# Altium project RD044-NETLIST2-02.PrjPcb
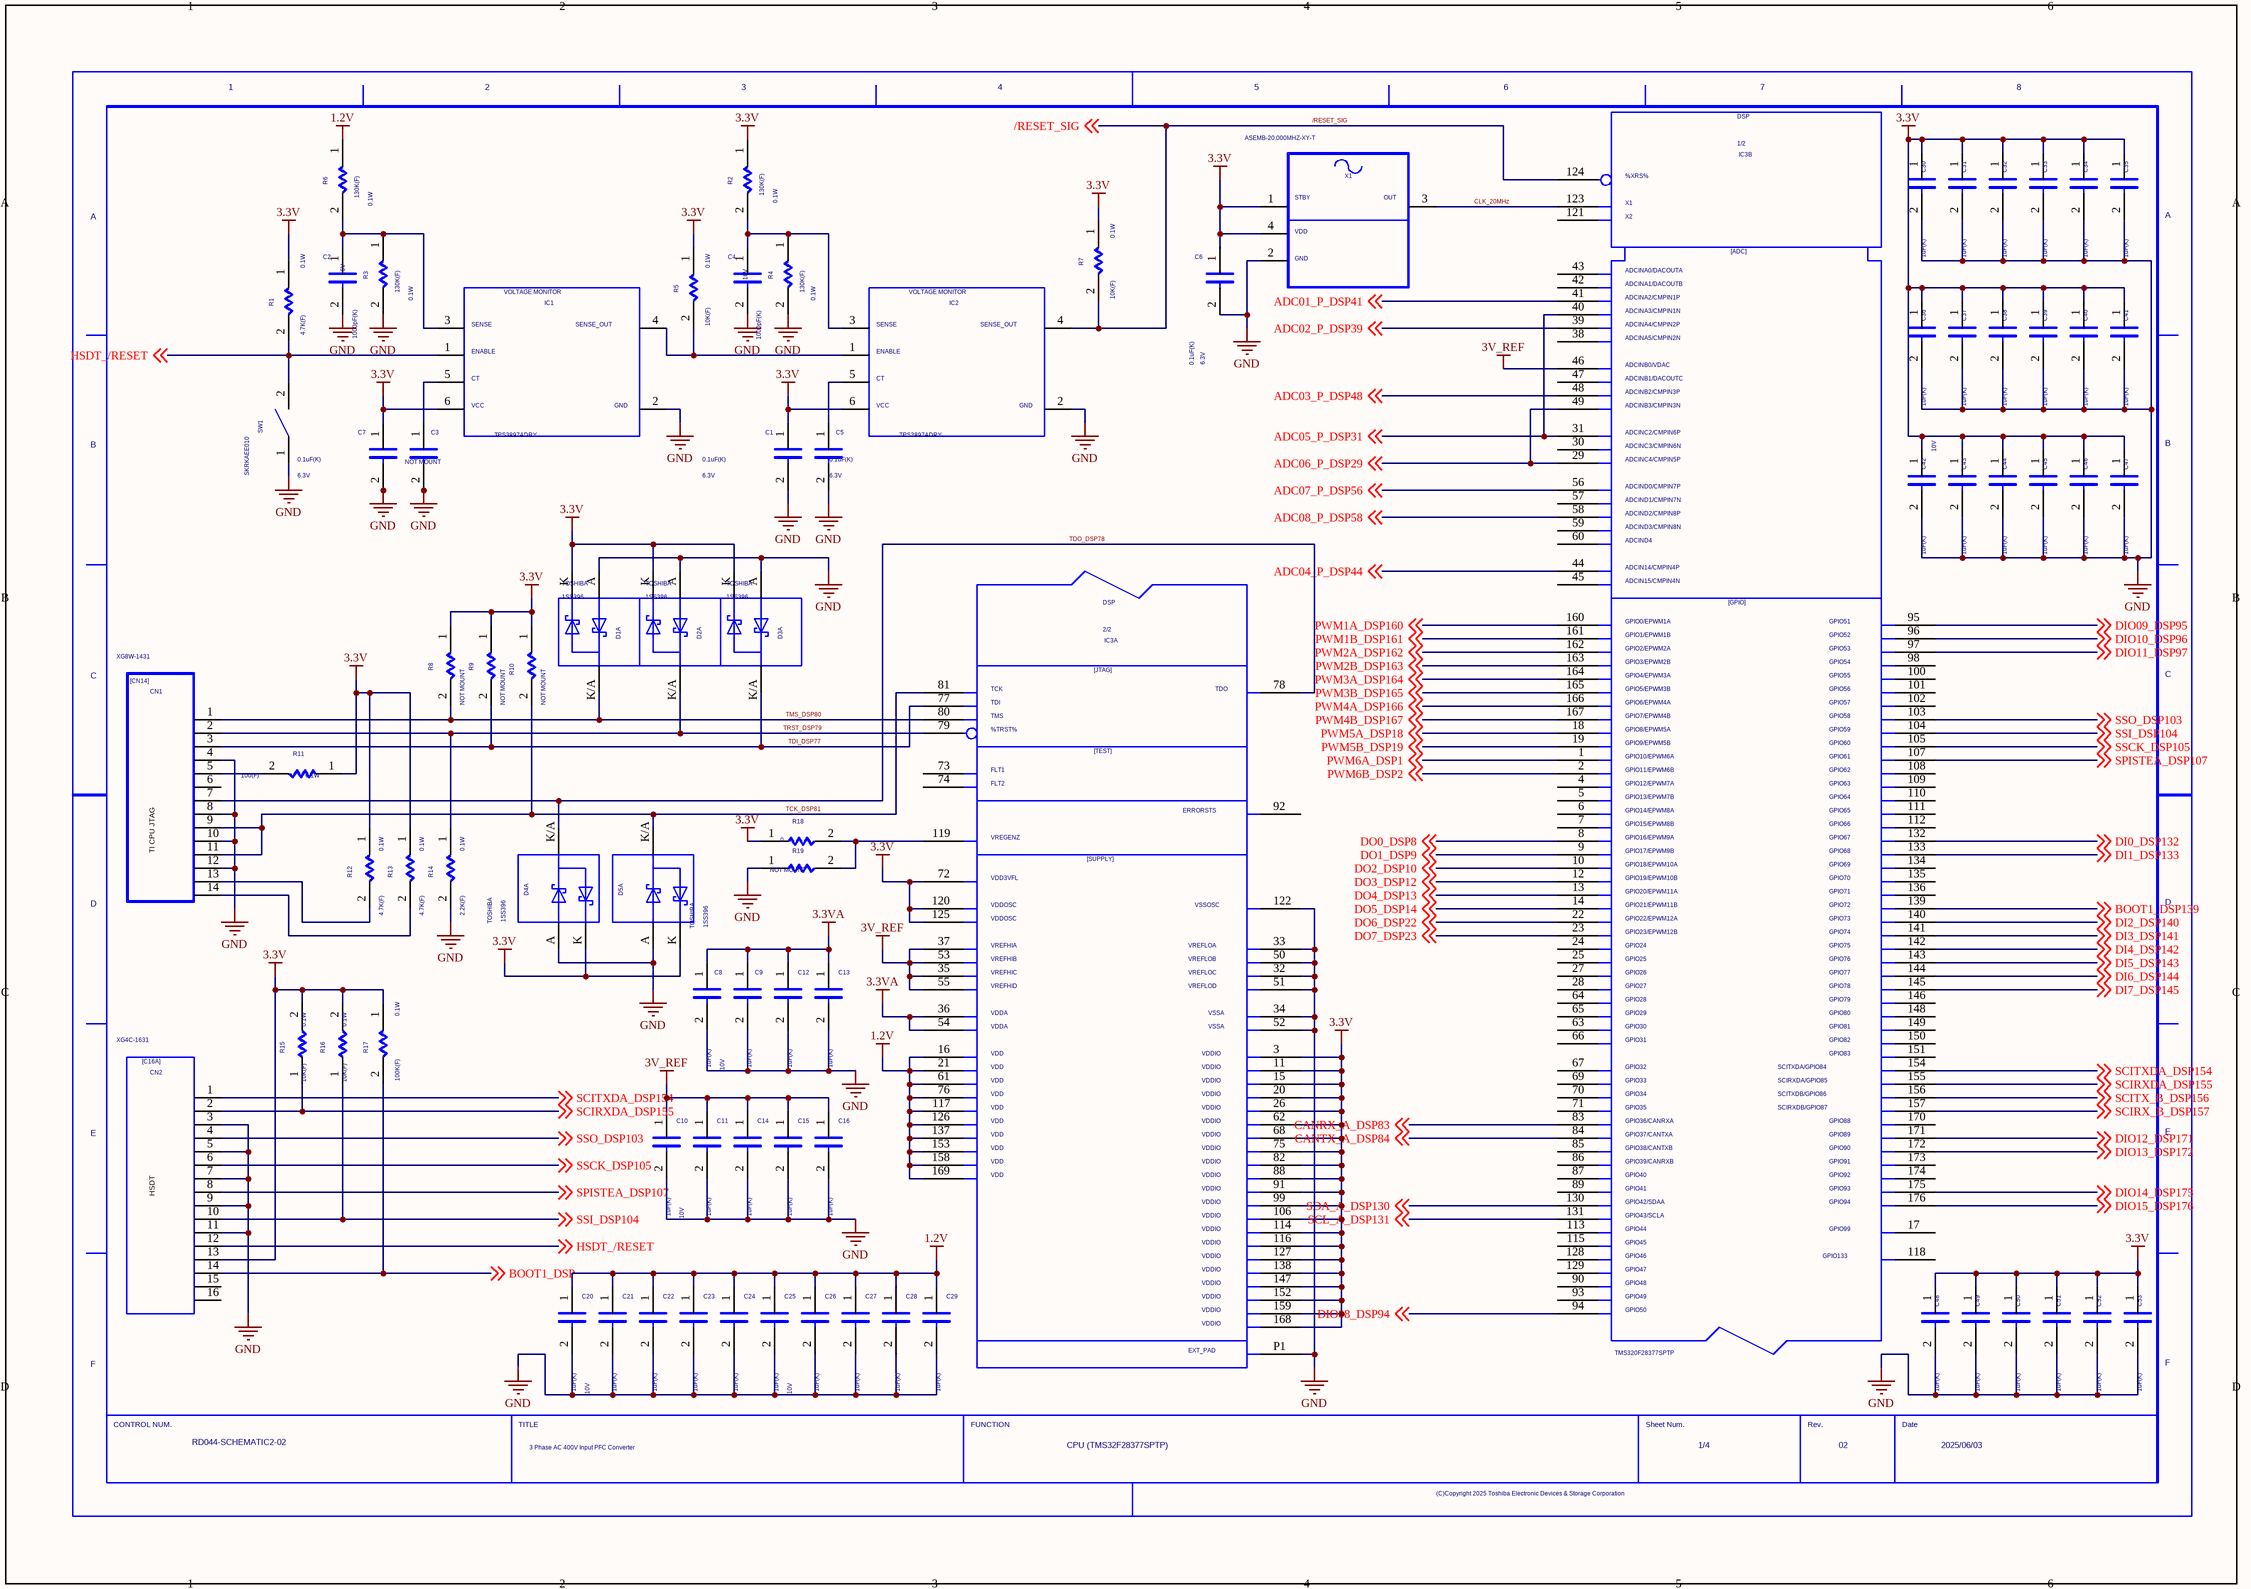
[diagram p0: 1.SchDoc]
4 sheets, 296 parts. Net scope: global (net labels, ports and power ports of the same name join across sheets).
Sheets:
  1.SchDoc
  2.SchDoc
  3.SchDoc
  4.SchDoc

## Sheet 1.SchDoc
size 420 x 297 mm

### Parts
(Parts that share a designator on the sheet are numbered #1, #2 ... from top to bottom, then left to right.)
C1  VAL1: 0.1uF(K)  VAL2: 6.3V  (hidden comment: C)
C2  VAL1: 1000pF(K)  VAL2: 16V  (hidden comment: C)
C3  NOTMOUNT: NOT MOUNT  (hidden comment: C)
C4  VAL1: 1000pF(K)  VAL2: 16V  (hidden comment: C)
C5  VAL1: 0.1uF(K)  VAL2: 6.3V  (hidden comment: C)
C6  VAL1: 0.1uF(K)  VAL2: 6.3V  (hidden comment: C)
C7  VAL1: 0.1uF(K)  VAL2: 6.3V  (hidden comment: C)
C8  VAL1: 1uF(K)  VAL2: 10V  (hidden comment: C)
C9  VAL1: 1uF(K)  (hidden comment: C)
C10  VAL1: 1uF(K)  VAL2: 10V  (hidden comment: C)
C11  VAL1: 1uF(K)  (hidden comment: C)
C12  VAL1: 1uF(K)  (hidden comment: C)
C13  VAL1: 1uF(K)  (hidden comment: C)
C14  VAL1: 1uF(K)  (hidden comment: C)
C15  VAL1: 1uF(K)  (hidden comment: C)
C16  VAL1: 1uF(K)  (hidden comment: C)
C20  VAL1: 1uF(K)  VAL2: 10V  (hidden comment: C)
C21  VAL1: 1uF(K)  (hidden comment: C)
C22  VAL1: 1uF(K)  (hidden comment: C)
C23  VAL1: 1uF(K)  (hidden comment: C)
C24  VAL1: 1uF(K)  (hidden comment: C)
C25  VAL1: 1uF(K)  VAL2: 10V  (hidden comment: C)
C26  VAL1: 1uF(K)  (hidden comment: C)
C27  VAL1: 1uF(K)  (hidden comment: C)
C28  VAL1: 1uF(K)  (hidden comment: C)
C29  VAL1: 1uF(K)  (hidden comment: C)
C30  VAL1: 1uF(K)  (hidden comment: C)
C31  VAL1: 1uF(K)  (hidden comment: C)
C32  VAL1: 1uF(K)  (hidden comment: C)
C33  VAL1: 1uF(K)  (hidden comment: C)
C34  VAL1: 1uF(K)  (hidden comment: C)
C35  VAL1: 1uF(K)  (hidden comment: C)
C36  VAL1: 1uF(K)  (hidden comment: C)
C37  VAL1: 1uF(K)  (hidden comment: C)
C38  VAL1: 1uF(K)  (hidden comment: C)
C39  VAL1: 1uF(K)  (hidden comment: C)
C40  VAL1: 1uF(K)  (hidden comment: C)
C41  VAL1: 1uF(K)  (hidden comment: C)
C42  VAL1: 1uF(K)  VAL2: 10V  (hidden comment: C)
C43  VAL1: 1uF(K)  (hidden comment: C)
C44  VAL1: 1uF(K)  (hidden comment: C)
C45  VAL1: 1uF(K)  (hidden comment: C)
C46  VAL1: 1uF(K)  (hidden comment: C)
C47  VAL1: 1uF(K)  (hidden comment: C)
C48  VAL1: 1uF(K)  (hidden comment: C)
C49  VAL1: 1uF(K)  (hidden comment: C)
C50  VAL1: 1uF(K)  (hidden comment: C)
C51  VAL1: 1uF(K)  (hidden comment: C)
C52  VAL1: 1uF(K)  (hidden comment: C)
C53  VAL1: 1uF(K)  (hidden comment: C)
CN1  VAL3: XG8W-1431  (hidden comment: CN14)
CN2  VAL3: XG4C-1631  (hidden comment: C16A)
D1  USERCOMPTEXT3: TOSHIBA  (hidden comment: 1SS396)  (part A of 3)
D2  USERCOMPTEXT3: TOSHIBA  (hidden comment: 1SS396)  (part A of 3)
D3  USERCOMPTEXT3: TOSHIBA  (hidden comment: 1SS396)  (part A of 3)
D4  USERCOMPTEXT3: TOSHIBA  (hidden comment: 1SS396)  (part A of 3)
D5  USERCOMPTEXT3: TOSHIBA  (hidden comment: 1SS396)  (part A of 3)
IC1  VAL3: TPS3897ADRY  (hidden comment: TPS3897)
IC2  VAL3: TPS3897ADRY  (hidden comment: TPS3897)
IC3  U320F28377_1  (value not drawn)  (parts A,B of 2)
R1  VAL2: 0.1W  VAL1: 4.7K(F)  (hidden comment: R)
R2  VAL2: 0.1W  VAL1: 130K(F)  (hidden comment: R)
R3  VAL2: 0.1W  VAL1: 130K(F)  (hidden comment: R)
R4  VAL2: 0.1W  VAL1: 130K(F)  (hidden comment: R)
R5  VAL2: 0.1W  VAL1: 10K(F)  (hidden comment: R)
R6  VAL2: 0.1W  VAL1: 130K(F)  (hidden comment: R)
R7  VAL2: 0.1W  VAL1: 10K(F)  (hidden comment: R)
R8  NOTMOUNT: NOT MOUNT  (hidden comment: R)
R9  NOTMOUNT: NOT MOUNT  (hidden comment: R)
R10  NOTMOUNT: NOT MOUNT  (hidden comment: R)
R11  VAL2: 0.1W  VAL1: 100(F)  (hidden comment: R)
R12  VAL2: 0.1W  VAL1: 4.7K(F)  (hidden comment: R)
R13  VAL2: 0.1W  VAL1: 4.7K(F)  (hidden comment: R)
R14  VAL2: 0.1W  VAL1: 2.2K(F)  (hidden comment: R)
R15  VAL2: 0.1W  VAL1: 10K(F)  (hidden comment: R)
R16  VAL2: 0.1W  VAL1: 10K(F)  (hidden comment: R)
R17  VAL2: 0.1W  VAL1: 100K(F)  (hidden comment: R)
R18  VAL1: 0  (hidden comment: R)
R19  NOTMOUNT: NOT MOUNT  (hidden comment: R)
SW1  VAL3: SKRKAEE010  (hidden comment: SW)
U?#1  DATE: 2025/06/03  DRAWINGNUMBER: RD044-SCHEMATIC2-02  TITLE: 3 Phase AC 400V Input PFC Converter  FUNCTION: CPU (TMS32F28377SPTP)  SHEETNUMBER: 1/4  REVISION: 02  (hidden comment: WAKU_DEF100_2018)
X1  VAL3: ASEMB-20.000MHZ-XY-T  (hidden comment: ASEMB)

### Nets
1.2V: C20.1 C21.1 C22.1 C23.1 C24.1 C25.1 C26.1 C27.1 C28.1 C29.1 IC3.16 IC3.21 IC3.61 IC3.76 IC3.117 IC3.126 IC3.137 IC3.153 IC3.158 IC3.169 R6.1
3.3V: C1.1 C6.1 C7.1 C30.1 C31.1 C32.1 C33.1 C34.1 C35.1 C36.1 C37.1 C38.1 C39.1 C40.1 C41.1 C42.1 C43.1 C44.1 C45.1 C46.1 C47.1 C48.1 C49.1 C50.1 C51.1 C52.1 C53.1 CN2.13 D1.K D2.K D3.K D4.K D5.K IC1.6 IC2.6 IC3.3 IC3.11 IC3.15 IC3.20 IC3.26 IC3.62 IC3.68 IC3.72 IC3.75 IC3.82 IC3.88 IC3.91 IC3.99 IC3.106 IC3.114 IC3.116 IC3.120 IC3.125 IC3.127 IC3.138 IC3.147 IC3.152 IC3.159 IC3.168 R1.1 R2.1 R5.1 R7.1 R8.1 R9.1 R10.1 R11.1 R12.1 R13.1 R15.2 R16.2 R17.1 R18.1 X1.1 X1.4
3.3VA: C8.1 C9.1 C12.1 C13.1 IC3.36 IC3.54
3V_REF: C10.1 C11.1 C14.1 C15.1 C16.1 IC3.35 IC3.37 IC3.46 IC3.53 IC3.55
GND: C1.2 C2.2 C3.2 C4.2 C5.2 C6.2 C7.2 C8.2 C9.2 C10.2 C11.2 C12.2 C13.2 C14.2 C15.2 C16.2 C20.2 C21.2 C22.2 C23.2 C24.2 C25.2 C26.2 C27.2 C28.2 C29.2 C30.2 C31.2 C32.2 C33.2 C34.2 C35.2 C36.2 C37.2 C38.2 C39.2 C40.2 C41.2 C42.2 C43.2 C44.2 C45.2 C46.2 C47.2 C48.2 C49.2 C50.2 C51.2 C52.2 C53.2 CN1.4 CN1.8 CN1.10 CN1.12 CN2.3 CN2.5 CN2.7 CN2.9 CN2.11 D1.A D2.A D3.A D4.A D5.A IC1.2 IC2.2 IC3.32 IC3.33 IC3.34 IC3.50 IC3.51 IC3.52 IC3.122 IC3.P1 R3.2 R4.2 R14.2 R19.1 SW1.1 X1.2
/RESET_SIG: IC2.4 IC3.124 R7.2 ; off-sheet /RESET_SIG
ADC01_P_DSP41: IC3.41 ; off-sheet ADC01_P_DSP41
ADC02_P_DSP39: IC3.39 ; off-sheet ADC02_P_DSP39
ADC03_P_DSP48: IC3.48 ; off-sheet ADC03_P_DSP48
ADC04_P_DSP44: IC3.44 ; off-sheet ADC04_P_DSP44
ADC05_P_DSP31: IC3.31 IC3.40 ; off-sheet ADC05_P_DSP31
ADC06_P_DSP29: IC3.29 IC3.49 ; off-sheet ADC06_P_DSP29
ADC07_P_DSP56: IC3.56 ; off-sheet ADC07_P_DSP56
ADC08_P_DSP58: IC3.58 ; off-sheet ADC08_P_DSP58
BOOT1_DSP: CN2.14 R17.2 ; off-sheet BOOT1_DSP
BOOT1_DSP139: IC3.139 ; off-sheet BOOT1_DSP139
CANRX_A_DSP83: IC3.83 ; off-sheet CANRX_A_DSP83
CANTX_A_DSP84: IC3.84 ; off-sheet CANTX_A_DSP84
CLK_20MHz: IC3.123 X1.3
DI0_DSP132: IC3.132 ; off-sheet DI0_DSP132
DI1_DSP133: IC3.133 ; off-sheet DI1_DSP133
DI2_DSP140: IC3.140 ; off-sheet DI2_DSP140
DI3_DSP141: IC3.141 ; off-sheet DI3_DSP141
DI4_DSP142: IC3.142 ; off-sheet DI4_DSP142
DI5_DSP143: IC3.143 ; off-sheet DI5_DSP143
DI6_DSP144: IC3.144 ; off-sheet DI6_DSP144
DI7_DSP145: IC3.145 ; off-sheet DI7_DSP145
DIO08_DSP94: IC3.94 ; off-sheet DIO08_DSP94
DIO09_DSP95: IC3.95 ; off-sheet DIO09_DSP95
DIO10_DSP96: IC3.96 ; off-sheet DIO10_DSP96
DIO11_DSP97: IC3.97 ; off-sheet DIO11_DSP97
DIO12_DSP171: IC3.171 ; off-sheet DIO12_DSP171
DIO13_DSP172: IC3.172 ; off-sheet DIO13_DSP172
DIO14_DSP175: IC3.175 ; off-sheet DIO14_DSP175
DIO15_DSP176: IC3.176 ; off-sheet DIO15_DSP176
DO0_DSP8: IC3.8 ; off-sheet DO0_DSP8
DO1_DSP9: IC3.9 ; off-sheet DO1_DSP9
DO2_DSP10: IC3.10 ; off-sheet DO2_DSP10
DO3_DSP12: IC3.12 ; off-sheet DO3_DSP12
DO4_DSP13: IC3.13 ; off-sheet DO4_DSP13
DO5_DSP14: IC3.14 ; off-sheet DO5_DSP14
DO6_DSP22: IC3.22 ; off-sheet DO6_DSP22
DO7_DSP23: IC3.23 ; off-sheet DO7_DSP23
HSDT_/RESET: CN2.12 IC1.1 R1.2 SW1.2 ; off-sheet HSDT_/RESET
N16607086: IC1.4 IC2.1 R5.2
N16607090: C4.1 IC2.3 R2.2 R4.1
N16607182: C2.1 IC1.3 R3.1 R6.2
N16607210: C5.1 IC2.5
N16608626: CN1.5 R11.2
N16609034: CN1.13 R12.2
N16609038: CN1.14 R13.2
N16609736: IC3.119 R18.2 R19.2
PWM1A_DSP160: IC3.160 ; off-sheet PWM1A_DSP160
PWM1B_DSP161: IC3.161 ; off-sheet PWM1B_DSP161
PWM2A_DSP162: IC3.162 ; off-sheet PWM2A_DSP162
PWM2B_DSP163: IC3.163 ; off-sheet PWM2B_DSP163
PWM3A_DSP164: IC3.164 ; off-sheet PWM3A_DSP164
PWM3B_DSP165: IC3.165 ; off-sheet PWM3B_DSP165
PWM4A_DSP166: IC3.166 ; off-sheet PWM4A_DSP166
PWM4B_DSP167: IC3.167 ; off-sheet PWM4B_DSP167
PWM5A_DSP18: IC3.18 ; off-sheet PWM5A_DSP18
PWM5B_DSP19: IC3.19 ; off-sheet PWM5B_DSP19
PWM6A_DSP1: IC3.1 ; off-sheet PWM6A_DSP1
PWM6B_DSP2: IC3.2 ; off-sheet PWM6B_DSP2
SCIRX_B_DSP157: IC3.157 ; off-sheet SCIRX_B_DSP157
SCIRXDA_DSP155: CN2.2 IC3.155 R15.1 ; off-sheet SCIRXDA_DSP155
SCITX_B_DSP156: IC3.156 ; off-sheet SCITX_B_DSP156
SCITXDA_DSP154: CN2.1 IC3.154 ; off-sheet SCITXDA_DSP154
SCL_A_DSP131: IC3.131 ; off-sheet SCL_A_DSP131
SDA_A_DSP130: IC3.130 ; off-sheet SDA_A_DSP130
SIG15: C3.1 IC1.5
SPISTEA_DSP107: CN2.8 IC3.107 ; off-sheet SPISTEA_DSP107
SSCK_DSP105: CN2.6 IC3.105 ; off-sheet SSCK_DSP105
SSI_DSP104: CN2.10 IC3.104 R16.1 ; off-sheet SSI_DSP104
SSO_DSP103: CN2.4 IC3.103 ; off-sheet SSO_DSP103
TCK_DSP81: CN1.9 CN1.11 D5.K/A IC3.81 R10.2
TDI_DSP77: CN1.3 D3.K/A IC3.77 R9.2
TDO_DSP78: CN1.7 D4.K/A IC3.78
TMS_DSP80: CN1.1 D1.K/A IC3.80 R8.2
TRST_DSP79: CN1.2 D2.K/A IC3.79 R14.1

Not connected (* = marked no-connect by the designer): CN1 6; CN2 15 16; IC3 4 5 6 7 17 24 25 27 28 30 38 42 43 45 47 57 59 60 63 64 65 66 67 69 70 71 73 74 85 86 87 89 90 92 93 98 100 101 102 108 109 110 111 112 113 115 118 121 128 129 134 135 136 146 148 149 150 151 170 173 174

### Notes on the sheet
- (near CN1) TI CPU JTAG
- (near CN2) HSDT

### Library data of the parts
C1 C5-C7 = C: OriginalSymbolOrigin: (2540,7620); CDBNAME: C-GRM155R70J104KA01D; USERCOMPTEXT1: 1005
C2 C4 = C: OriginalSymbolOrigin: (2540,7620); CDBNAME: C-GRM188R71C102KA01D; USERCOMPTEXT1: 1608
C3 = C: OriginalSymbolOrigin: (2540,7620); CDBNAME: C-1608_NM; USERCOMPTEXT1: 1608
C8 C10 C20 C25 C42 = C: OriginalSymbolOrigin: (2540,7620); CDBNAME: C-GRM188R71A105KA61D; USERCOMPTEXT1: 1608
C9 C11-C16 C21-C24 C26-C41 C43-C53 = C: OriginalSymbolOrigin: (2540,7620); CDBNAME: C-GRM188R71A105KA61D
CN1 = CN14: OriginalSymbolOrigin: (2540,45720); CDBNAME: CN-XG8W-1431; MAXGCOUNT: 1; ADSCNVFLAG: ON
CN2 = C16A: SAVEAREA0: -32851,-599,52300,52191; TIME: 12:01:18; UPDATEUSER: fukuda-y; UPDATETIME: 13:44:49; SAVECOUNT: 2; OriginalSymbolOrigin: (2540,48260); CDBNAME: CN-XG4C-1631
D1-D5 = 1SS396: SAVECOUNT: 7; SAVEAREA0: -5465,-437,27678,21425; TIME: 18:51:12; UPDATEUSER: cae; UPDATETIME: 10:39:29; OriginalSymbolOrigin: (5080,17780); CDBNAME: D-1SS396_AK
IC1 IC2 = TPS3897: SAVEAREA0: -10817,-344,54055,33349; TIME: 16:54:57; UPDATEUSER: cae; UPDATETIME: 13:48:08; SAVECOUNT: 66; OriginalSymbolOrigin: (5080,30480); CDBNAME: IC-TPS3897ADRY
IC3 = U320F28377_1: SAVEAREA0: -157495,-2464,228972,238585; SAVECOUNT: 59; TIME: 10:04:23; UPDATEUSER: cae; UPDATETIME: 18:05:54; OriginalSymbolOrigin: (7620,233680); CaptureCellPackProp: U320F28377_1A; VAL3: TMS320F28377SPTP; FUNCN: TMS320F_2_function; CDBNAME: IC-TMS320F28377SPTP
R1 R12 R13 = R: OriginalSymbolOrigin: (5080,5080); CDBNAME: R-ERJ3EKF4701V; USERCOMPTEXT1: 1608
R2 = R: OriginalSymbolOrigin: (5080,5080); CDBNAME: R-ERA3AEB304V; USERCOMPTEXT1: 1608
R3 R17 = R: OriginalSymbolOrigin: (5080,5080); CDBNAME: R-ERJ3EKF1003V; USERCOMPTEXT1: 1608
R4 = R: OriginalSymbolOrigin: (5080,5080); CDBNAME: R-ERA3AEB563V; USERCOMPTEXT1: 1608
R5 R7 R15 R16 = R: OriginalSymbolOrigin: (5080,5080); CDBNAME: R-ERJ3EKF1002V; USERCOMPTEXT1: 1608
R6 = R: OriginalSymbolOrigin: (5080,5080); CDBNAME: R-ERA3AEB134V; USERCOMPTEXT1: 1608
R8-R10 R19 = R: OriginalSymbolOrigin: (5080,5080); CDBNAME: R-1608_NM; USERCOMPTEXT1: 1608
R11 = R: OriginalSymbolOrigin: (5080,5080); CDBNAME: R-ERJ3EKF1000V; USERCOMPTEXT1: 1608
R14 = R: OriginalSymbolOrigin: (5080,5080); CDBNAME: R-ERJ3EKF2201V; USERCOMPTEXT1: 1608
R18 = R: OriginalSymbolOrigin: (5080,5080); CDBNAME: R-RK73Z1JTTD
SW1 = SW: SAVEAREA0: -3361,-153,18383,13055; SAVECOUNT: 49; TIME: 15:02:55; UPDATEUSER: fukuda-y; UPDATETIME: 10:01:15; OriginalSymbolOrigin: (5080,5080); CDBNAME: SW-SKRKAEE010; MAXGCOUNT: 1; ADSCNVFLAG: ON
U?#1 = WAKU_DEF100_2018: PLOTTIME: HH:MM; SAVEAREA0: -45080,-4508,463680,304612; TIME: 13:54:34; UPDATEUSER: e5025010; UPDATETIME: 15:56:23; SAVECOUNT: 4; OriginalSymbolOrigin: (10160,284480)
X1 = ASEMB: SAVEAREA0: -13388,-318,46493,30783; TIME: 14:56:21; UPDATEUSER: cae; UPDATETIME: 14:57:23; SAVECOUNT: 2; OriginalSymbolOrigin: (5080,27940); CDBNAME: X-ASEMB-20.000MHZ-XY-T

## Sheet 2.SchDoc
size 420 x 297 mm
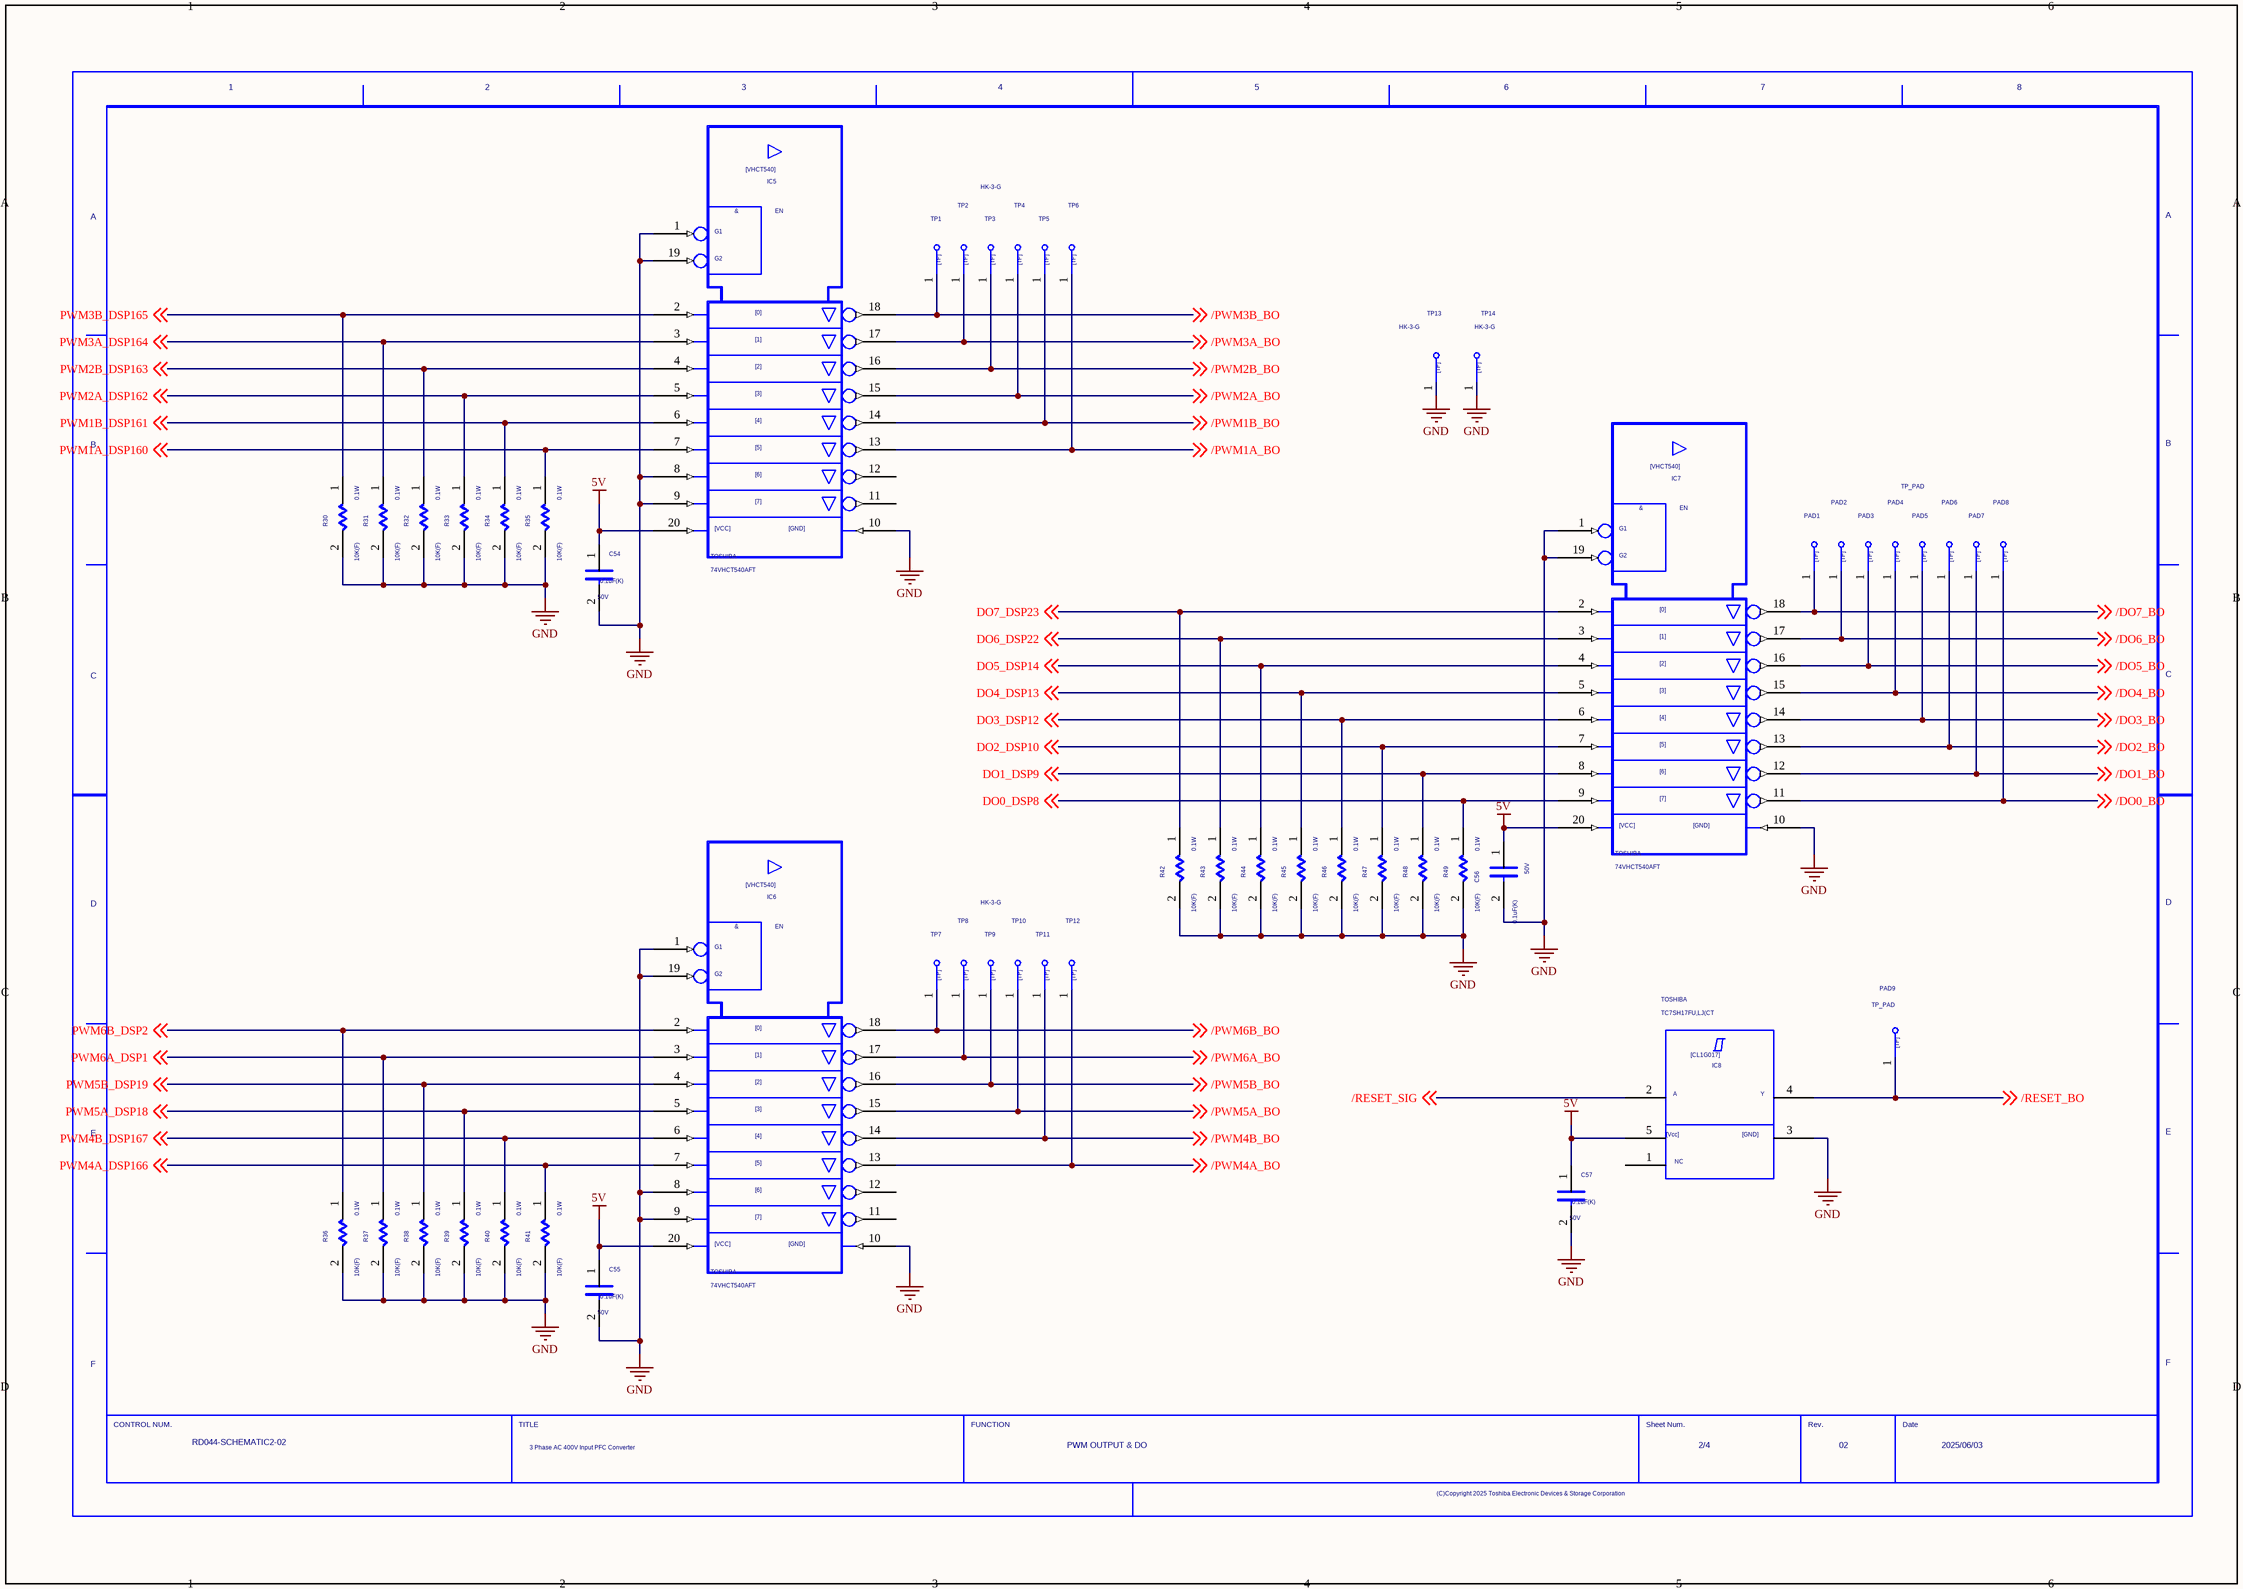
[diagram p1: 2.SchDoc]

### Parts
(Parts that share a designator on the sheet are numbered #1, #2 ... from top to bottom, then left to right.)
C54  VAL1: 0.1uF(K)  VAL2: 50V  (hidden comment: C)
C55  VAL1: 0.1uF(K)  VAL2: 50V  (hidden comment: C)
C56  VAL1: 0.1uF(K)  VAL2: 50V  (hidden comment: C)
C57  VAL1: 0.1uF(K)  VAL2: 50V  (hidden comment: C)
IC5  USERCOMPTEXT3: TOSHIBA  VAL3: 74VHCT540AFT  (hidden comment: VHC540)
IC6  USERCOMPTEXT3: TOSHIBA  VAL3: 74VHCT540AFT  (hidden comment: VHC540)
IC7  USERCOMPTEXT3: TOSHIBA  VAL3: 74VHCT540AFT  (hidden comment: VHC540)
IC8  USERCOMPTEXT3: TOSHIBA  VAL3: TC7SH17FU,LJ(CT  (hidden comment: CL1G017)
PAD1  TP  (value not drawn)
PAD2  VAL3: TP_PAD  (hidden comment: TP)
PAD3  TP  (value not drawn)
PAD4  TP  (value not drawn)
PAD5  TP  (value not drawn)
PAD6  TP  (value not drawn)
PAD7  TP  (value not drawn)
PAD8  TP  (value not drawn)
PAD9  VAL3: TP_PAD  (hidden comment: TP)
R30  VAL2: 0.1W  VAL1: 10K(F)  (hidden comment: R)
R31  VAL2: 0.1W  VAL1: 10K(F)  (hidden comment: R)
R32  VAL2: 0.1W  VAL1: 10K(F)  (hidden comment: R)
R33  VAL2: 0.1W  VAL1: 10K(F)  (hidden comment: R)
R34  VAL2: 0.1W  VAL1: 10K(F)  (hidden comment: R)
R35  VAL2: 0.1W  VAL1: 10K(F)  (hidden comment: R)
R36  VAL2: 0.1W  VAL1: 10K(F)  (hidden comment: R)
R37  VAL2: 0.1W  VAL1: 10K(F)  (hidden comment: R)
R38  VAL2: 0.1W  VAL1: 10K(F)  (hidden comment: R)
R39  VAL2: 0.1W  VAL1: 10K(F)  (hidden comment: R)
R40  VAL2: 0.1W  VAL1: 10K(F)  (hidden comment: R)
R41  VAL2: 0.1W  VAL1: 10K(F)  (hidden comment: R)
R42  VAL2: 0.1W  VAL1: 10K(F)  (hidden comment: R)
R43  VAL2: 0.1W  VAL1: 10K(F)  (hidden comment: R)
R44  VAL2: 0.1W  VAL1: 10K(F)  (hidden comment: R)
R45  VAL2: 0.1W  VAL1: 10K(F)  (hidden comment: R)
R46  VAL2: 0.1W  VAL1: 10K(F)  (hidden comment: R)
R47  VAL2: 0.1W  VAL1: 10K(F)  (hidden comment: R)
R48  VAL2: 0.1W  VAL1: 10K(F)  (hidden comment: R)
R49  VAL2: 0.1W  VAL1: 10K(F)  (hidden comment: R)
TP1  TP  (value not drawn)
TP2  VAL3: HK-3-G  (hidden comment: TP)
TP3  TP  (value not drawn)
TP4  TP  (value not drawn)
TP5  TP  (value not drawn)
TP6  TP  (value not drawn)
TP7  TP  (value not drawn)
TP8  VAL3: HK-3-G  (hidden comment: TP)
TP9  TP  (value not drawn)
TP10  TP  (value not drawn)
TP11  TP  (value not drawn)
TP12  TP  (value not drawn)
TP13  VAL3: HK-3-G  (hidden comment: TP)
TP14  VAL3: HK-3-G  (hidden comment: TP)
U?#2  DATE: 2025/06/03  DRAWINGNUMBER: RD044-SCHEMATIC2-02  TITLE: 3 Phase AC 400V Input PFC Converter  FUNCTION: PWM OUTPUT & DO  SHEETNUMBER: 2/4  REVISION: 02  (hidden comment: WAKU_DEF100_2018)

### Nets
5V: C54.1 C55.1 C56.1 C57.1 IC5.20 IC6.20 IC7.20 IC8.5
GND: C54.2 C55.2 C56.2 C57.2 IC5.1 IC5.8 IC5.9 IC5.10 IC5.19 IC6.1 IC6.8 IC6.9 IC6.10 IC6.19 IC7.1 IC7.10 IC7.19 IC8.3 R30.2 R31.2 R32.2 R33.2 R34.2 R35.2 R36.2 R37.2 R38.2 R39.2 R40.2 R41.2 R42.2 R43.2 R44.2 R45.2 R46.2 R47.2 R48.2 R49.2 TP13.1 TP14.1
/DO0_BO: IC7.11 PAD8.1 ; off-sheet /DO0_BO
/DO1_BO: IC7.12 PAD7.1 ; off-sheet /DO1_BO
/DO2_BO: IC7.13 PAD6.1 ; off-sheet /DO2_BO
/DO3_BO: IC7.14 PAD5.1 ; off-sheet /DO3_BO
/DO4_BO: IC7.15 PAD4.1 ; off-sheet /DO4_BO
/DO5_BO: IC7.16 PAD3.1 ; off-sheet /DO5_BO
/DO6_BO: IC7.17 PAD2.1 ; off-sheet /DO6_BO
/DO7_BO: IC7.18 PAD1.1 ; off-sheet /DO7_BO
/PWM1A_BO: IC5.13 TP6.1 ; off-sheet /PWM1A_BO
/PWM1B_BO: IC5.14 TP5.1 ; off-sheet /PWM1B_BO
/PWM2A_BO: IC5.15 TP4.1 ; off-sheet /PWM2A_BO
/PWM2B_BO: IC5.16 TP3.1 ; off-sheet /PWM2B_BO
/PWM3A_BO: IC5.17 TP2.1 ; off-sheet /PWM3A_BO
/PWM3B_BO: IC5.18 TP1.1 ; off-sheet /PWM3B_BO
/PWM4A_BO: IC6.13 TP12.1 ; off-sheet /PWM4A_BO
/PWM4B_BO: IC6.14 TP11.1 ; off-sheet /PWM4B_BO
/PWM5A_BO: IC6.15 TP10.1 ; off-sheet /PWM5A_BO
/PWM5B_BO: IC6.16 TP9.1 ; off-sheet /PWM5B_BO
/PWM6A_BO: IC6.17 TP8.1 ; off-sheet /PWM6A_BO
/PWM6B_BO: IC6.18 TP7.1 ; off-sheet /PWM6B_BO
/RESET_BO: IC8.4 PAD9.1 ; off-sheet /RESET_BO
/RESET_SIG: IC8.2 ; off-sheet /RESET_SIG
DO0_DSP8: IC7.9 R49.1 ; off-sheet DO0_DSP8
DO1_DSP9: IC7.8 R48.1 ; off-sheet DO1_DSP9
DO2_DSP10: IC7.7 R47.1 ; off-sheet DO2_DSP10
DO3_DSP12: IC7.6 R46.1 ; off-sheet DO3_DSP12
DO4_DSP13: IC7.5 R45.1 ; off-sheet DO4_DSP13
DO5_DSP14: IC7.4 R44.1 ; off-sheet DO5_DSP14
DO6_DSP22: IC7.3 R43.1 ; off-sheet DO6_DSP22
DO7_DSP23: IC7.2 R42.1 ; off-sheet DO7_DSP23
PWM1A_DSP160: IC5.7 R35.1 ; off-sheet PWM1A_DSP160
PWM1B_DSP161: IC5.6 R34.1 ; off-sheet PWM1B_DSP161
PWM2A_DSP162: IC5.5 R33.1 ; off-sheet PWM2A_DSP162
PWM2B_DSP163: IC5.4 R32.1 ; off-sheet PWM2B_DSP163
PWM3A_DSP164: IC5.3 R31.1 ; off-sheet PWM3A_DSP164
PWM3B_DSP165: IC5.2 R30.1 ; off-sheet PWM3B_DSP165
PWM4A_DSP166: IC6.7 R41.1 ; off-sheet PWM4A_DSP166
PWM4B_DSP167: IC6.6 R40.1 ; off-sheet PWM4B_DSP167
PWM5A_DSP18: IC6.5 R39.1 ; off-sheet PWM5A_DSP18
PWM5B_DSP19: IC6.4 R38.1 ; off-sheet PWM5B_DSP19
PWM6A_DSP1: IC6.3 R37.1 ; off-sheet PWM6A_DSP1
PWM6B_DSP2: IC6.2 R36.1 ; off-sheet PWM6B_DSP2

Not connected (* = marked no-connect by the designer): IC5 11 12; IC6 11 12; IC8 1

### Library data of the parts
C54-C57 = C: OriginalSymbolOrigin: (2540,7620); CDBNAME: C-GRM188R71H104KA93D; USERCOMPTEXT1: 1608
IC5-IC7 = VHC540: SAVEAREA0: -64373,-927,110287,89788; TIME: 09:37:32; UPDATEUSER: cae; SAVECOUNT: 1; OriginalSymbolOrigin: (7620,83820); CDBNAME: IC-74VHCT540AFT
IC8 = CL1G017: TIME: 16:09:43; UPDATEUSER: tomizawa-y; UPDATETIME: 12:13:51; SAVECOUNT: 12; SAVEAREA0: -8892,-376,44463,33313; OriginalSymbolOrigin: (7620,30480); MAXGCOUNT: 1; CDBNAME: IC-TC7SH17F; ADSCNVFLAG: ON
PAD1 PAD7 PAD8 = TP: TIME: 16:12:21; UPDATEUSER: fukuda-y; UPDATETIME: 16:18:11; SAVECOUNT: 2; SAVEAREA0: -242,-92,12810,7836; OriginalSymbolOrigin: (0,7620); CDBNAME: TP-PAD1.0; VAL3: TP_PAD
PAD2 PAD9 = TP: TIME: 16:12:21; UPDATEUSER: fukuda-y; UPDATETIME: 16:18:11; SAVECOUNT: 2; SAVEAREA0: -242,-92,12810,7836; OriginalSymbolOrigin: (0,7620); CDBNAME: TP-PAD1.0
PAD3-PAD6 = TP: TIME: 16:12:21; UPDATEUSER: fukuda-y; UPDATETIME: 16:18:11; SAVECOUNT: 2; SAVEAREA0: -242,-92,12810,7836; OriginalSymbolOrigin: (0,7620); CDBNAME: TP-PAD1.0; VAL3: HK-3-G
R30-R49 = R: as R5 on sheet 1
TP1 TP3-TP7 TP9-TP12 = TP: TIME: 16:12:21; UPDATEUSER: fukuda-y; UPDATETIME: 16:18:11; SAVECOUNT: 2; SAVEAREA0: -242,-92,12810,7836; OriginalSymbolOrigin: (0,7620); CDBNAME: TP-HK-3-G; VAL3: HK-3-G
TP2 TP8 TP13 TP14 = TP: TIME: 16:12:21; UPDATEUSER: fukuda-y; UPDATETIME: 16:18:11; SAVECOUNT: 2; SAVEAREA0: -242,-92,12810,7836; OriginalSymbolOrigin: (0,7620); CDBNAME: TP-HK-3-G
U?#2 = WAKU_DEF100_2018: as U?#1 on sheet 1

## Sheet 3.SchDoc
size 420 x 297 mm
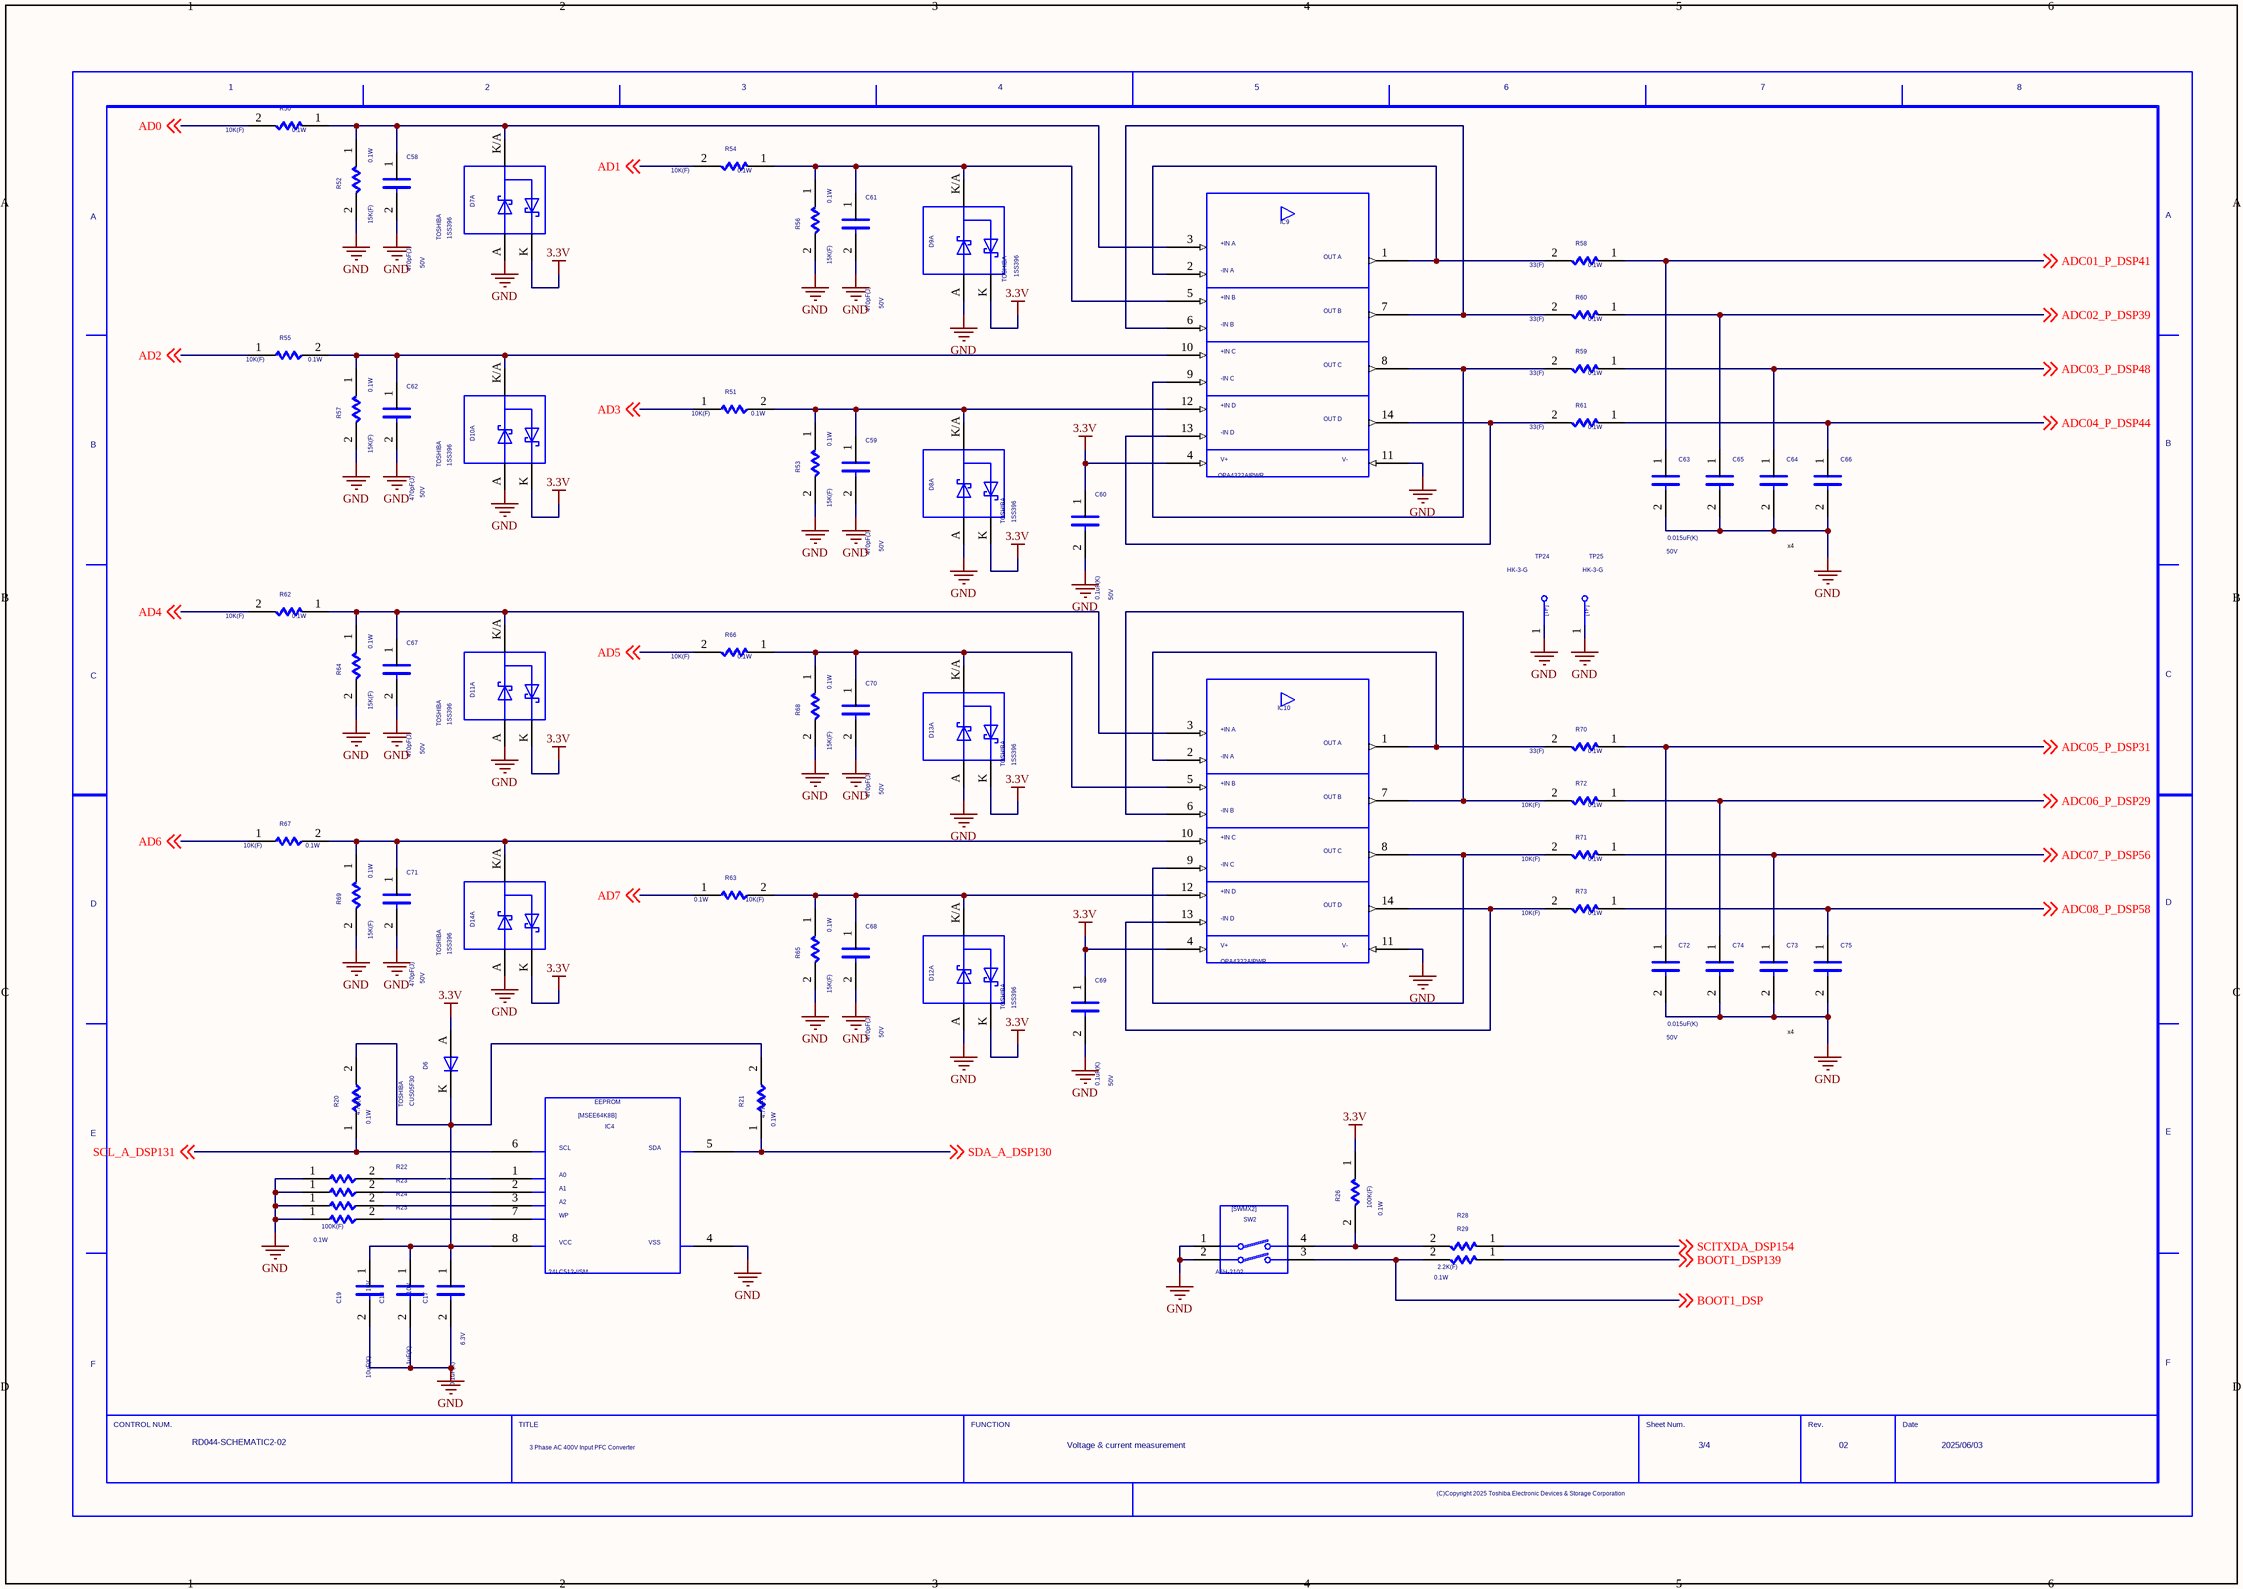
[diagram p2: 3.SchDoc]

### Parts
(Parts that share a designator on the sheet are numbered #1, #2 ... from top to bottom, then left to right.)
C17  VAL1: 0.1uF(K)  VAL2: 6.3V  (hidden comment: C)
C18  VAL1: 1uF(K)  VAL2: 10V  (hidden comment: C)
C19  VAL1: 10uF(K)  VAL2: 10V  (hidden comment: C)
C58  VAL1: 470pF(J)  VAL2: 50V  (hidden comment: C)
C59  VAL1: 470pF(J)  VAL2: 50V  (hidden comment: C)
C60  VAL1: 0.1uF(K)  VAL2: 50V  (hidden comment: C)
C61  VAL1: 470pF(J)  VAL2: 50V  (hidden comment: C)
C62  VAL1: 470pF(J)  VAL2: 50V  (hidden comment: C)
C63  VAL1: 0.015uF(K)  VAL2: 50V  (hidden comment: C)
C64  C  (value not drawn)
C65  C  (value not drawn)
C66  C  (value not drawn)
C67  VAL1: 470pF(J)  VAL2: 50V  (hidden comment: C)
C68  VAL1: 470pF(J)  VAL2: 50V  (hidden comment: C)
C69  VAL1: 0.1uF(K)  VAL2: 50V  (hidden comment: C)
C70  VAL1: 470pF(J)  VAL2: 50V  (hidden comment: C)
C71  VAL1: 470pF(J)  VAL2: 50V  (hidden comment: C)
C72  VAL1: 0.015uF(K)  VAL2: 50V  (hidden comment: C)
C73  C  (value not drawn)
C74  C  (value not drawn)
C75  C  (value not drawn)
D6  USERCOMPTEXT3: TOSHIBA  VAL3: CUS05F30  (hidden comment: DIODE)
D7  USERCOMPTEXT3: TOSHIBA  (hidden comment: 1SS396)  (part A of 3)
D8  USERCOMPTEXT3: TOSHIBA  (hidden comment: 1SS396)  (part A of 3)
D9  USERCOMPTEXT3: TOSHIBA  (hidden comment: 1SS396)  (part A of 3)
D10  USERCOMPTEXT3: TOSHIBA  (hidden comment: 1SS396)  (part A of 3)
D11  USERCOMPTEXT3: TOSHIBA  (hidden comment: 1SS396)  (part A of 3)
D12  USERCOMPTEXT3: TOSHIBA  (hidden comment: 1SS396)  (part A of 3)
D13  USERCOMPTEXT3: TOSHIBA  (hidden comment: 1SS396)  (part A of 3)
D14  USERCOMPTEXT3: TOSHIBA  (hidden comment: 1SS396)  (part A of 3)
IC4  VAL3: 24LC512-I/SM  (hidden comment: MSEE64K8B)
IC9  VAL3: OPA4322AIPWR  (hidden comment: OPA4322A)
IC10  VAL3: OPA4322AIPWR  (hidden comment: OPA4322A)
R20  VAL2: 0.1W  VAL1: 4.7K(F)  (hidden comment: R)
R21  VAL2: 0.1W  VAL1: 4.7K(F)  (hidden comment: R)
R22  R  (value not drawn)
R23  R  (value not drawn)
R24  R  (value not drawn)
R25  VAL2: 0.1W  VAL1: 100K(F)  (hidden comment: R)
R26  VAL2: 0.1W  VAL1: 100K(F)  (hidden comment: R)
R28  R  (value not drawn)
R29  VAL2: 0.1W  VAL1: 2.2K(F)  (hidden comment: R)
R50  VAL2: 0.1W  VAL1: 10K(F)  (hidden comment: R)
R51  VAL2: 0.1W  VAL1: 10K(F)  (hidden comment: R)
R52  VAL2: 0.1W  VAL1: 15K(F)  (hidden comment: R)
R53  VAL2: 0.1W  VAL1: 15K(F)  (hidden comment: R)
R54  VAL2: 0.1W  VAL1: 10K(F)  (hidden comment: R)
R55  VAL2: 0.1W  VAL1: 10K(F)  (hidden comment: R)
R56  VAL2: 0.1W  VAL1: 15K(F)  (hidden comment: R)
R57  VAL2: 0.1W  VAL1: 15K(F)  (hidden comment: R)
R58  VAL2: 0.1W  VAL1: 33(F)  (hidden comment: R)
R59  VAL2: 0.1W  VAL1: 33(F)  (hidden comment: R)
R60  VAL2: 0.1W  VAL1: 33(F)  (hidden comment: R)
R61  VAL2: 0.1W  VAL1: 33(F)  (hidden comment: R)
R62  VAL2: 0.1W  VAL1: 10K(F)  (hidden comment: R)
R63  VAL2: 0.1W  VAL1: 10K(F)  (hidden comment: R)
R64  VAL2: 0.1W  VAL1: 15K(F)  (hidden comment: R)
R65  VAL2: 0.1W  VAL1: 15K(F)  (hidden comment: R)
R66  VAL2: 0.1W  VAL1: 10K(F)  (hidden comment: R)
R67  VAL2: 0.1W  VAL1: 10K(F)  (hidden comment: R)
R68  VAL2: 0.1W  VAL1: 15K(F)  (hidden comment: R)
R69  VAL2: 0.1W  VAL1: 15K(F)  (hidden comment: R)
R70  VAL2: 0.1W  VAL1: 33(F)  (hidden comment: R)
R71  VAL2: 0.1W  VAL1: 10K(F)  (hidden comment: R)
R72  VAL2: 0.1W  VAL1: 10K(F)  (hidden comment: R)
R73  VAL2: 0.1W  VAL1: 10K(F)  (hidden comment: R)
SW2  VAL3: A6H-2102  (hidden comment: SWMX2)
TP24  VAL3: HK-3-G  (hidden comment: TP)
TP25  VAL3: HK-3-G  (hidden comment: TP)
U?#3  DATE: 2025/06/03  DRAWINGNUMBER: RD044-SCHEMATIC2-02  TITLE: 3 Phase AC 400V Input PFC Converter  FUNCTION: Voltage & current measurement  SHEETNUMBER: 3/4  REVISION: 02  (hidden comment: WAKU_DEF100_2018)

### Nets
3.3V: C60.1 C69.1 D6.A D7.K D8.K D9.K D10.K D11.K D12.K D13.K D14.K IC9.4 IC10.4 R26.1
GND: C17.2 C18.2 C19.2 C58.2 C59.2 C60.2 C61.2 C62.2 C63.2 C64.2 C65.2 C66.2 C67.2 C68.2 C69.2 C70.2 C71.2 C72.2 C73.2 C74.2 C75.2 D7.A D8.A D9.A D10.A D11.A D12.A D13.A D14.A IC4.4 IC9.11 IC10.11 R22.1 R23.1 R24.1 R25.1 R52.2 R53.2 R56.2 R57.2 R64.2 R65.2 R68.2 R69.2 SW2.1 SW2.2 TP24.1 TP25.1
AD0: R50.2 ; off-sheet AD0
AD1: R54.2 ; off-sheet AD1
AD2: R55.1 ; off-sheet AD2
AD3: R51.1 ; off-sheet AD3
AD4: R62.2 ; off-sheet AD4
AD5: R66.2 ; off-sheet AD5
AD6: R67.1 ; off-sheet AD6
AD7: R63.1 ; off-sheet AD7
ADC01_P_DSP41: C63.1 R58.1 ; off-sheet ADC01_P_DSP41
ADC02_P_DSP39: C65.1 R60.1 ; off-sheet ADC02_P_DSP39
ADC03_P_DSP48: C64.1 R59.1 ; off-sheet ADC03_P_DSP48
ADC04_P_DSP44: C66.1 R61.1 ; off-sheet ADC04_P_DSP44
ADC05_P_DSP31: C72.1 R70.1 ; off-sheet ADC05_P_DSP31
ADC06_P_DSP29: C74.1 R72.1 ; off-sheet ADC06_P_DSP29
ADC07_P_DSP56: C73.1 R71.1 ; off-sheet ADC07_P_DSP56
ADC08_P_DSP58: C75.1 R73.1 ; off-sheet ADC08_P_DSP58
BOOT1_DSP: R29.2 SW2.3 ; off-sheet BOOT1_DSP
BOOT1_DSP139: R29.1 ; off-sheet BOOT1_DSP139
N16610346: C17.1 C18.1 C19.1 D6.K IC4.8 R20.2 R21.2
N16610376: IC4.1 R22.2
N16610420: IC4.2 R23.2
N16610428: IC4.7 R25.2
N16610486: IC4.3 R24.2
N16610930: R26.2 R28.2 SW2.4
N16624647: C59.1 D8.K/A IC9.12 R51.2 R53.1
N16624651: C58.1 D7.K/A IC9.3 R50.1 R52.1
N16624783: IC9.1 IC9.2 R58.2
N16624799: IC9.13 IC9.14 R61.2
N16625013: C61.1 D9.K/A IC9.5 R54.1 R56.1
N16625021: C62.1 D10.K/A IC9.10 R55.2 R57.1
N16625097: IC9.6 IC9.7 R60.2
N16625113: IC9.8 IC9.9 R59.2
N16625873: C67.1 D11.K/A IC10.3 R62.1 R64.1
N16626013: IC10.1 IC10.2 R70.2
N16626029: IC10.13 IC10.14 R73.2
N16626045: C68.1 D12.K/A IC10.12 R63.2 R65.1
N16626273: C70.1 D13.K/A IC10.5 R66.1 R68.1
N16626281: C71.1 D14.K/A IC10.10 R67.2 R69.1
N16626357: IC10.6 IC10.7 R72.2
N16626365: IC10.8 IC10.9 R71.2
SCITXDA_DSP154: R28.1 ; off-sheet SCITXDA_DSP154
SCL_A_DSP131: IC4.6 R20.1 ; off-sheet SCL_A_DSP131
SDA_A_DSP130: IC4.5 R21.1 ; off-sheet SDA_A_DSP130

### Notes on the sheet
- x4

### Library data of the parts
C17 = C: as C1 on sheet 1
C18 = C: as C8 on sheet 1
C19 = C: OriginalSymbolOrigin: (2540,7620); CDBNAME: C-GRM188R61A106KE69D; USERCOMPTEXT1: 1608
C58 C59 C61 C62 C67 C68 C70 C71 = C: OriginalSymbolOrigin: (2540,7620); CDBNAME: C-GRM1885C1H471JA01D; USERCOMPTEXT1: 1608
C60 C69 = C: as C54 on sheet 2
C63 C72 = C: OriginalSymbolOrigin: (2540,7620); CDBNAME: C-GRM188R11H153KA01D; USERCOMPTEXT1: 1608
C64-C66 C73-C75 = C: VAL1: 0.015uF(K); VAL2: 50V; OriginalSymbolOrigin: (2540,7620); CDBNAME: C-GRM188R11H153KA01D; USERCOMPTEXT1: 1608
D6 = DIODE: SAVEAREA0: -1337,-97,13924,7829; SAVECOUNT: 4; TIME: 14:49:55; UPDATEUSER: cae; UPDATETIME: 13:41:08; OriginalSymbolOrigin: (5080,5080); CDBNAME: D-CUS05F30
D7-D14 = 1SS396: as D1 on sheet 1
IC4 = MSEE64K8B: SAVECOUNT: 8; SAVEAREA0: -9998,-458,55119,39162; TIME: 10:18:07; UPDATEUSER: 19990028; UPDATETIME: 09:15:23; OriginalSymbolOrigin: (7620,35560); MAXGCOUNT: 1; CDBNAME: IC-24LC512-I_SM; ADSCNVFLAG: ON
IC9 IC10 = OPA4322A: SAVECOUNT: 28; SAVEAREA0: -34439,-609,80338,59004; TIME: 15:40:02; UPDATEUSER: cae; UPDATETIME: 16:49:13; OriginalSymbolOrigin: (7620,55880); CDBNAME: IC-OPA4322AIPWR
R20 R21 = R: as R1 on sheet 1
R22-R24 = R: VAL2: 0.1W; VAL1: 100K(F); OriginalSymbolOrigin: (5080,5080); CDBNAME: R-ERJ3EKF1003V; USERCOMPTEXT1: 1608
R25 R26 = R: as R3 on sheet 1
R28 = R: VAL2: 0.1W; VAL1: 2.2K(F); OriginalSymbolOrigin: (5080,5080); CDBNAME: R-ERJ3EKF2201V; USERCOMPTEXT1: 1608
R29 = R: as R14 on sheet 1
R50 R51 R54 R55 R62 R63 R66 R67 = R: as R5 on sheet 1
R52 R53 R56 R57 R64 R65 R68 R69 = R: OriginalSymbolOrigin: (5080,5080); CDBNAME: R-ERJ3EKF1502V; USERCOMPTEXT1: 1608
R58-R61 R70-R73 = R: OriginalSymbolOrigin: (5080,5080); CDBNAME: R-ERJ3EKF33R0V; USERCOMPTEXT1: 1608
SW2 = SWMX2: OriginalSymbolOrigin: (5080,15240); CDBNAME: SW-A6H-2102
TP24 TP25 = TP: as TP2 on sheet 2
U?#3 = WAKU_DEF100_2018: PLOTTIME: HH:MM; SAVEAREA0: -45080,-4508,463680,304612; TIME: 13:54:34; UPDATEUSER: e5025010; UPDATETIME: 16:01:41; SAVECOUNT: 4; OriginalSymbolOrigin: (10160,284480); SHTSAVECOUNT: 6

## Sheet 4.SchDoc
size 420 x 297 mm
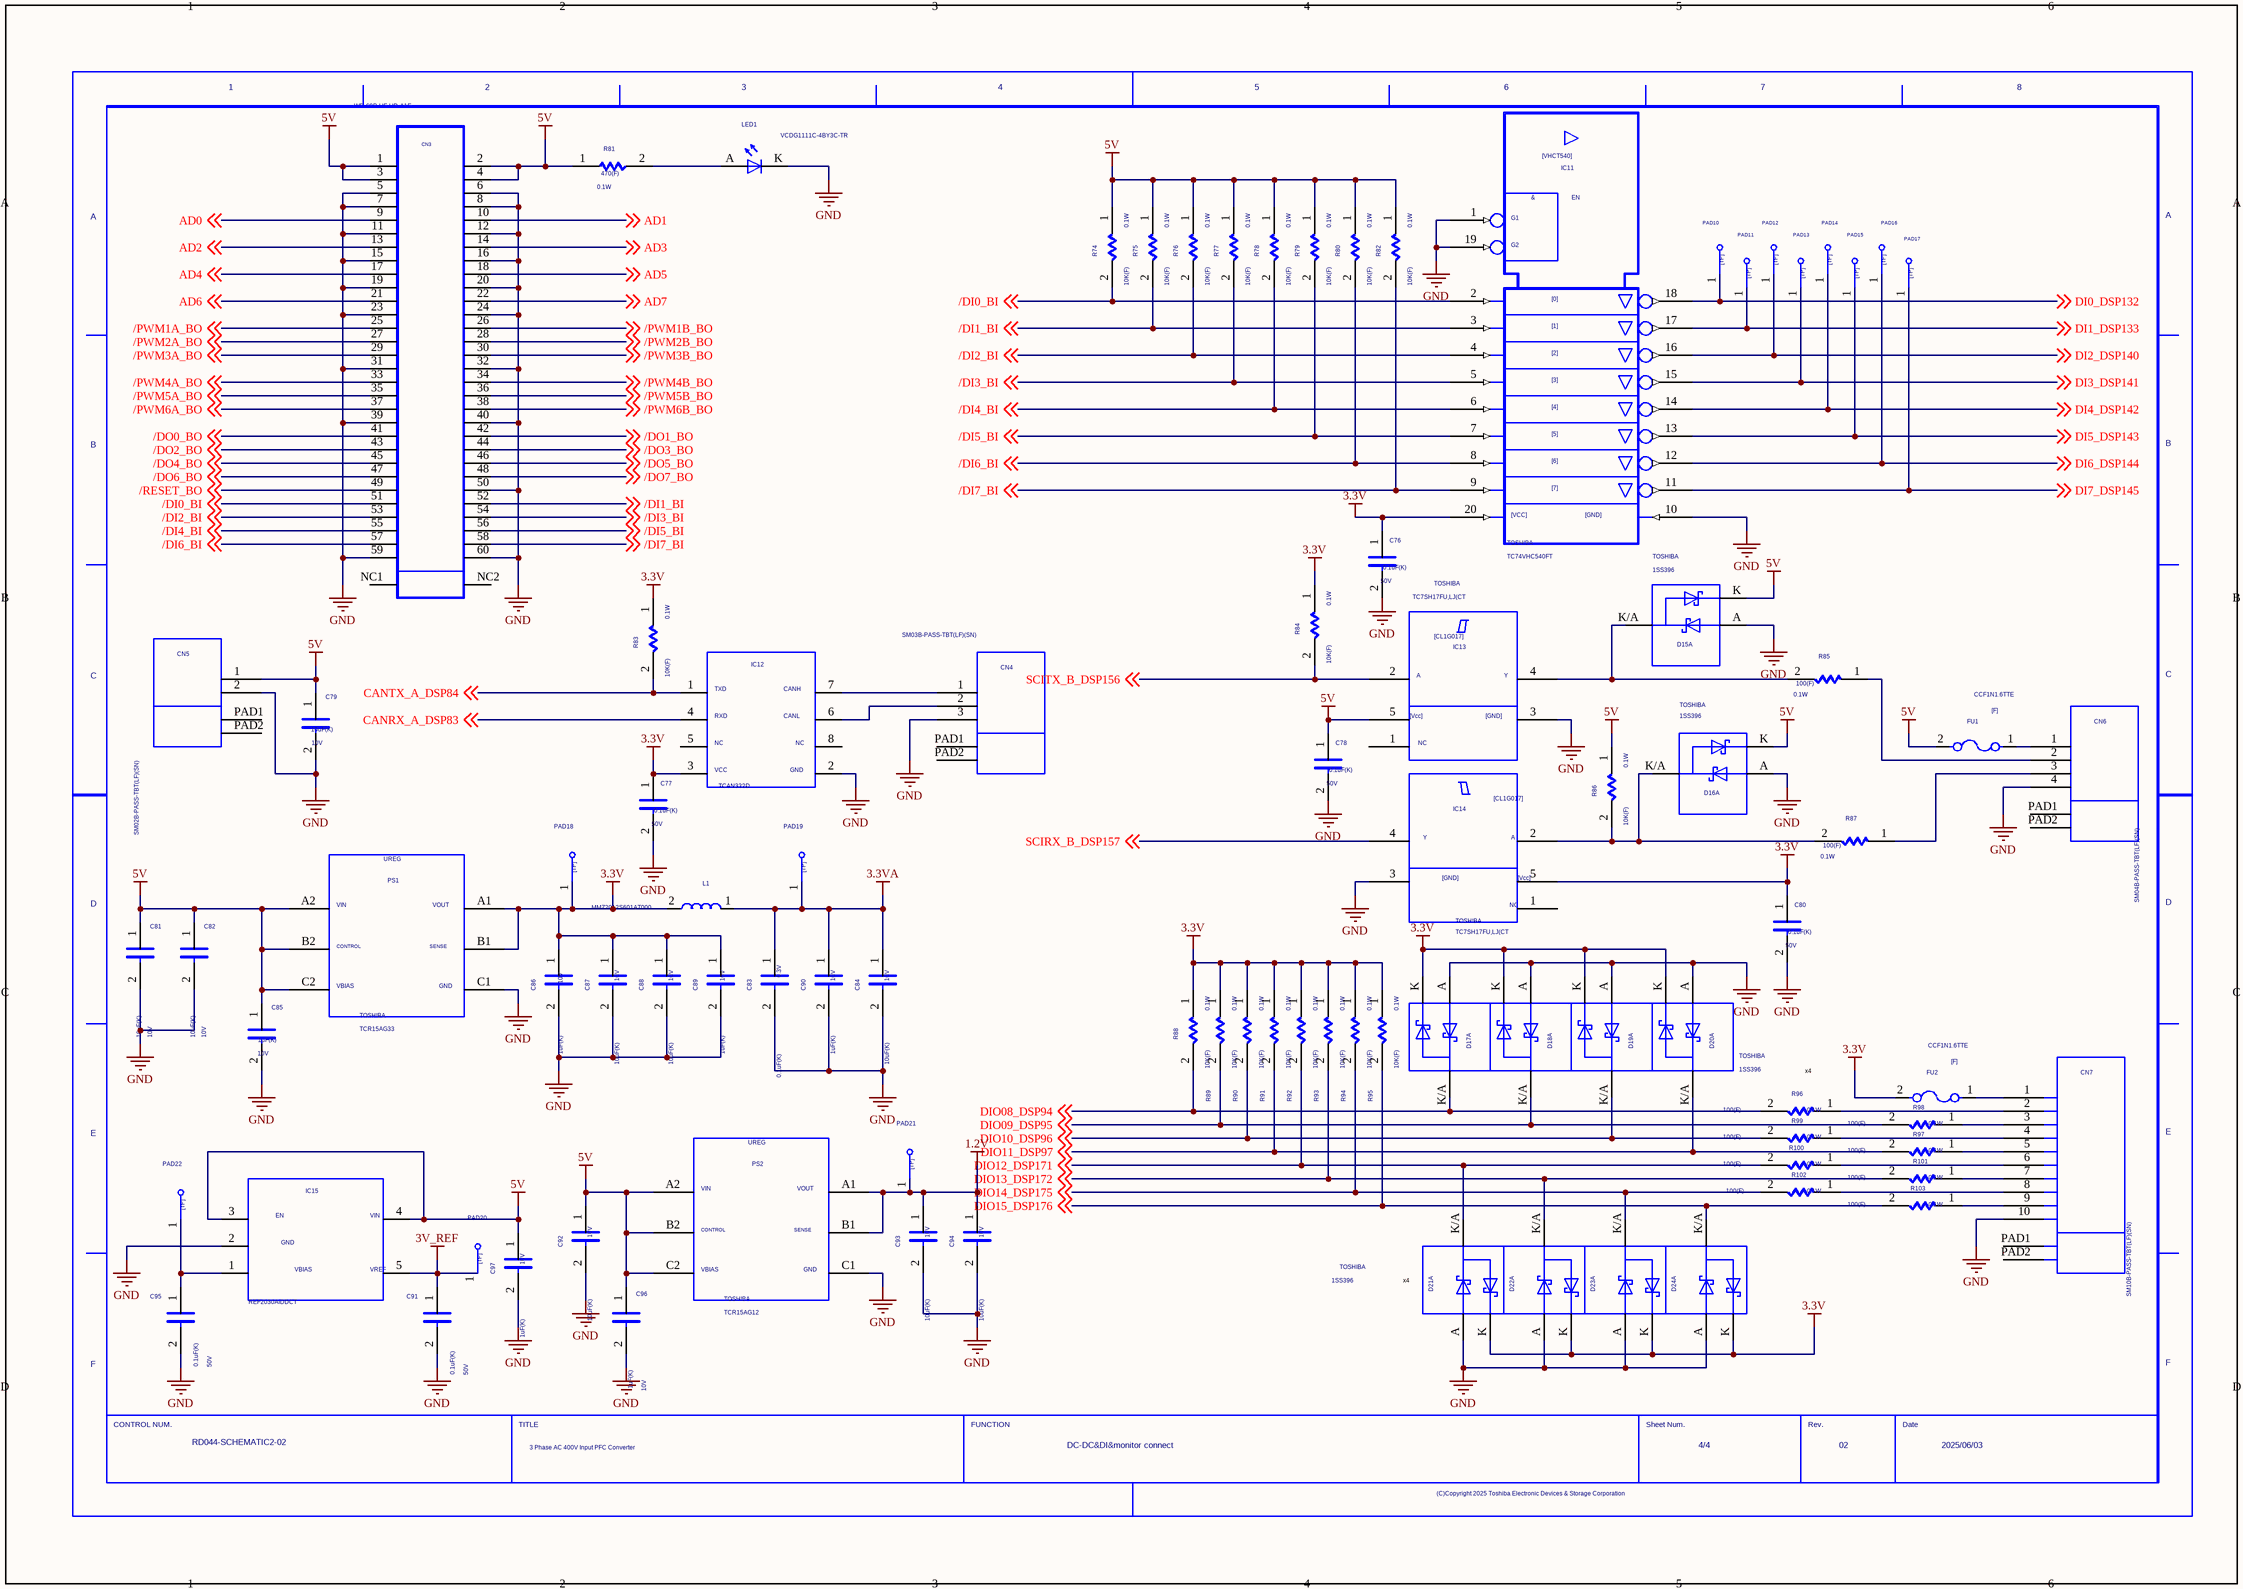
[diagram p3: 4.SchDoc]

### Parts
(Parts that share a designator on the sheet are numbered #1, #2 ... from top to bottom, then left to right.)
C76  VAL1: 0.1uF(K)  VAL2: 50V  (hidden comment: C)
C77  VAL1: 0.1uF(K)  VAL2: 50V  (hidden comment: C)
C78  VAL1: 0.1uF(K)  VAL2: 50V  (hidden comment: C)
C79  VAL1: 10uF(K)  VAL2: 10V  (hidden comment: C)
C80  VAL1: 0.1uF(K)  VAL2: 50V  (hidden comment: C)
C81  VAL1: 10uF(K)  VAL2: 10V  (hidden comment: C)
C82  VAL1: 10uF(K)  VAL2: 10V  (hidden comment: C)
C83  VAL1: 0.1uF(K)  VAL2: 6.3V  (hidden comment: C)
C84  VAL1: 10uF(K)  VAL2: 10V  (hidden comment: C)
C85  VAL1: 1uF(K)  VAL2: 10V  (hidden comment: C)
C86  VAL1: 1uF(K)  VAL2: 10V  (hidden comment: C)
C87  VAL1: 10uF(K)  VAL2: 10V  (hidden comment: C)
C88  VAL1: 10uF(K)  VAL2: 10V  (hidden comment: C)
C89  VAL1: 1uF(K)  VAL2: 10V  (hidden comment: C)
C90  VAL1: 1uF(K)  VAL2: 10V  (hidden comment: C)
C91  VAL1: 0.1uF(K)  VAL2: 50V  (hidden comment: C)
C92  VAL1: 10uF(K)  VAL2: 10V  (hidden comment: C)
C93  VAL1: 10uF(K)  VAL2: 10V  (hidden comment: C)
C94  VAL1: 10uF(K)  VAL2: 10V  (hidden comment: C)
C95  VAL1: 0.1uF(K)  VAL2: 50V  (hidden comment: C)
C96  VAL1: 1uF(K)  VAL2: 10V  (hidden comment: C)
C97  VAL1: 1uF(K)  VAL2: 10V  (hidden comment: C)
CN3  VAL3: WR-60P-HF-HD-A1E  (hidden comment: WR-60P)
CN4  VAL3: SM03B-PASS-TBT(LF)(SN)  (hidden comment: BM03B-PASS)
CN5  VAL3: SM02B-PASS-TBT(LF)(SN)  (hidden comment: BM02B-PASS)
CN6  VAL3: SM04B-PASS-TBT(LF)(SN)  (hidden comment: BM04B-PASS)
CN7  VAL3: SM10B-PASS-TBT(LF)(SN)  (hidden comment: SM10B-PASS)
D15  USERCOMPTEXT3: TOSHIBA  (hidden comment: 1SS396)  (part A of 3)
D16  USERCOMPTEXT3: TOSHIBA  (hidden comment: 1SS396)  (part A of 3)
D17  1SS396  (value not drawn)  (part A of 3)
D18  1SS396  (value not drawn)  (part A of 3)
D19  1SS396  (value not drawn)  (part A of 3)
D20  USERCOMPTEXT3: TOSHIBA  (hidden comment: 1SS396)  (part A of 3)
D21  USERCOMPTEXT3: TOSHIBA  (hidden comment: 1SS396)  (part A of 3)
D22  1SS396  (value not drawn)  (part A of 3)
D23  1SS396  (value not drawn)  (part A of 3)
D24  1SS396  (value not drawn)  (part A of 3)
FU1  VAL3: CCF1N1.6TTE  (hidden comment: F)
FU2  VAL3: CCF1N1.6TTE  (hidden comment: F)
IC11  USERCOMPTEXT3: TOSHIBA  VAL3: TC74VHC540FT  (hidden comment: VHC540)
IC12  TCAN332D
IC13  USERCOMPTEXT3: TOSHIBA  VAL3: TC7SH17FU,LJ(CT  (hidden comment: CL1G017)
IC14  USERCOMPTEXT3: TOSHIBA  VAL3: TC7SH17FU,LJ(CT  (hidden comment: CL1G017)
IC15  VAL3: REF2030AIDDCT  (hidden comment: REF)
L1  VAL3: MMZ2012S601AT000  (hidden comment: L)
LED1  VAL3: VCDG1111C-4BY3C-TR  (hidden comment: VCDG1111C)
PAD10  TP  (value not drawn)
PAD11  TP  (value not drawn)
PAD12  TP  (value not drawn)
PAD13  TP  (value not drawn)
PAD14  TP  (value not drawn)
PAD15  TP  (value not drawn)
PAD16  TP  (value not drawn)
PAD17  TP  (value not drawn)
PAD18  TP  (value not drawn)
PAD19  TP  (value not drawn)
PAD20  TP  (value not drawn)
PAD21  TP  (value not drawn)
PAD22  TP  (value not drawn)
PS1  USERCOMPTEXT3: TOSHIBA  VAL3: TCR15AG33  (hidden comment: L15AG)
PS2  USERCOMPTEXT3: TOSHIBA  VAL3: TCR15AG12  (hidden comment: L15AG)
R74  VAL2: 0.1W  VAL1: 10K(F)  (hidden comment: R)
R75  VAL2: 0.1W  VAL1: 10K(F)  (hidden comment: R)
R76  VAL2: 0.1W  VAL1: 10K(F)  (hidden comment: R)
R77  VAL2: 0.1W  VAL1: 10K(F)  (hidden comment: R)
R78  VAL2: 0.1W  VAL1: 10K(F)  (hidden comment: R)
R79  VAL2: 0.1W  VAL1: 10K(F)  (hidden comment: R)
R80  VAL2: 0.1W  VAL1: 10K(F)  (hidden comment: R)
R81  VAL2: 0.1W  VAL1: 470(F)  (hidden comment: R)
R82  VAL2: 0.1W  VAL1: 10K(F)  (hidden comment: R)
R83  VAL2: 0.1W  VAL1: 10K(F)  (hidden comment: R)
R84  VAL2: 0.1W  VAL1: 10K(F)  (hidden comment: R)
R85  VAL2: 0.1W  VAL1: 100(F)  (hidden comment: R)
R86  VAL2: 0.1W  VAL1: 10K(F)  (hidden comment: R)
R87  VAL2: 0.1W  VAL1: 100(F)  (hidden comment: R)
R88  VAL2: 0.1W  VAL1: 10K(F)  (hidden comment: R)
R89  VAL2: 0.1W  VAL1: 10K(F)  (hidden comment: R)
R90  VAL2: 0.1W  VAL1: 10K(F)  (hidden comment: R)
R91  VAL2: 0.1W  VAL1: 10K(F)  (hidden comment: R)
R92  VAL2: 0.1W  VAL1: 10K(F)  (hidden comment: R)
R93  VAL2: 0.1W  VAL1: 10K(F)  (hidden comment: R)
R94  VAL2: 0.1W  VAL1: 10K(F)  (hidden comment: R)
R95  VAL2: 0.1W  VAL1: 10K(F)  (hidden comment: R)
R96  VAL2: 0.1W  VAL1: 100(F)  (hidden comment: R)
R97  VAL2: 0.1W  VAL1: 100(F)  (hidden comment: R)
R98  VAL2: 0.1W  VAL1: 100(F)  (hidden comment: R)
R99  VAL2: 0.1W  VAL1: 100(F)  (hidden comment: R)
R100  VAL2: 0.1W  VAL1: 100(F)  (hidden comment: R)
R101  VAL2: 0.1W  VAL1: 100(F)  (hidden comment: R)
R102  VAL2: 0.1W  VAL1: 100(F)  (hidden comment: R)
R103  VAL2: 0.1W  VAL1: 100(F)  (hidden comment: R)
U?#4  DATE: 2025/06/03  DRAWINGNUMBER: RD044-SCHEMATIC2-02  TITLE: 3 Phase AC 400V Input PFC Converter  FUNCTION: DC-DC&DI&monitor connect  SHEETNUMBER: 4/4  REVISION: 02  (hidden comment: WAKU_DEF100_2018)

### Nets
1.2V: C93.1 C94.1 PAD21.1 PS2.A1 PS2.B1
3.3V: C76.1 C77.1 C80.1 C86.1 C87.1 C88.1 C89.1 D17.K D18.K D19.K D20.K D21.K D22.K D23.K D24.K FU2.2 IC11.20 IC12.3 IC14.5 L1.2 PAD18.1 PS1.A1 PS1.B1 R83.1 R84.1 R88.1 R89.1 R90.1 R91.1 R92.1 R93.1 R94.1 R95.1
3.3VA: C83.1 C84.1 C90.1 L1.1 PAD19.1
3V_REF: C91.1 IC15.5 PAD20.1
5V: C78.1 C79.1 C81.1 C82.1 C85.1 C92.1 C96.1 C97.1 CN3.1 CN3.2 CN3.3 CN3.4 CN5.1 D15.K D16.K FU1.2 IC13.5 IC15.3 IC15.4 PS1.A2 PS1.B2 PS1.C2 PS2.A2 PS2.B2 PS2.C2 R74.1 R75.1 R76.1 R77.1 R78.1 R79.1 R80.1 R81.1 R82.1 R86.1
GND: C76.2 C77.2 C78.2 C79.2 C80.2 C81.2 C82.2 C83.2 C84.2 C85.2 C86.2 C87.2 C88.2 C89.2 C90.2 C91.2 C92.2 C93.2 C94.2 C95.2 C96.2 C97.2 CN3.5 CN3.6 CN3.7 CN3.8 CN3.11 CN3.12 CN3.15 CN3.16 CN3.19 CN3.20 CN3.23 CN3.24 CN3.31 CN3.32 CN3.39 CN3.40 CN3.50 CN3.59 CN3.60 CN4.3 CN5.2 CN6.4 CN7.10 D15.A D16.A D17.A D18.A D19.A D20.A D21.A D22.A D23.A D24.A IC11.1 IC11.10 IC11.19 IC12.2 IC13.3 IC14.3 IC15.2 LED1.K PS1.C1 PS2.C1
/DI0_BI: CN3.51 IC11.2 R74.2 ; off-sheet /DI0_BI
/DI1_BI: CN3.52 IC11.3 R75.2 ; off-sheet /DI1_BI
/DI2_BI: CN3.53 IC11.4 R76.2 ; off-sheet /DI2_BI
/DI3_BI: CN3.54 IC11.5 R77.2 ; off-sheet /DI3_BI
/DI4_BI: CN3.55 IC11.6 R78.2 ; off-sheet /DI4_BI
/DI5_BI: CN3.56 IC11.7 R79.2 ; off-sheet /DI5_BI
/DI6_BI: CN3.57 IC11.8 R80.2 ; off-sheet /DI6_BI
/DI7_BI: CN3.58 IC11.9 R82.2 ; off-sheet /DI7_BI
/DO0_BO: CN3.41 ; off-sheet /DO0_BO
/DO1_BO: CN3.42 ; off-sheet /DO1_BO
/DO2_BO: CN3.43 ; off-sheet /DO2_BO
/DO3_BO: CN3.44 ; off-sheet /DO3_BO
/DO4_BO: CN3.45 ; off-sheet /DO4_BO
/DO5_BO: CN3.46 ; off-sheet /DO5_BO
/DO6_BO: CN3.47 ; off-sheet /DO6_BO
/DO7_BO: CN3.48 ; off-sheet /DO7_BO
/PWM1A_BO: CN3.25 ; off-sheet /PWM1A_BO
/PWM1B_BO: CN3.26 ; off-sheet /PWM1B_BO
/PWM2A_BO: CN3.27 ; off-sheet /PWM2A_BO
/PWM2B_BO: CN3.28 ; off-sheet /PWM2B_BO
/PWM3A_BO: CN3.29 ; off-sheet /PWM3A_BO
/PWM3B_BO: CN3.30 ; off-sheet /PWM3B_BO
/PWM4A_BO: CN3.33 ; off-sheet /PWM4A_BO
/PWM4B_BO: CN3.34 ; off-sheet /PWM4B_BO
/PWM5A_BO: CN3.35 ; off-sheet /PWM5A_BO
/PWM5B_BO: CN3.36 ; off-sheet /PWM5B_BO
/PWM6A_BO: CN3.37 ; off-sheet /PWM6A_BO
/PWM6B_BO: CN3.38 ; off-sheet /PWM6B_BO
/RESET_BO: CN3.49 ; off-sheet /RESET_BO
AD0: CN3.9 ; off-sheet AD0
AD1: CN3.10 ; off-sheet AD1
AD2: CN3.13 ; off-sheet AD2
AD3: CN3.14 ; off-sheet AD3
AD4: CN3.17 ; off-sheet AD4
AD5: CN3.18 ; off-sheet AD5
AD6: CN3.21 ; off-sheet AD6
AD7: CN3.22 ; off-sheet AD7
CANRX_A_DSP83: IC12.4 ; off-sheet CANRX_A_DSP83
CANTX_A_DSP84: IC12.1 R83.2 ; off-sheet CANTX_A_DSP84
DI0_DSP132: IC11.18 PAD10.1 ; off-sheet DI0_DSP132
DI1_DSP133: IC11.17 PAD11.1 ; off-sheet DI1_DSP133
DI2_DSP140: IC11.16 PAD12.1 ; off-sheet DI2_DSP140
DI3_DSP141: IC11.15 PAD13.1 ; off-sheet DI3_DSP141
DI4_DSP142: IC11.14 PAD14.1 ; off-sheet DI4_DSP142
DI5_DSP143: IC11.13 PAD15.1 ; off-sheet DI5_DSP143
DI6_DSP144: IC11.12 PAD16.1 ; off-sheet DI6_DSP144
DI7_DSP145: IC11.11 PAD17.1 ; off-sheet DI7_DSP145
DIO08_DSP94: D17.K/A R88.2 R96.2 ; off-sheet DIO08_DSP94
DIO09_DSP95: D18.K/A R89.2 R98.2 ; off-sheet DIO09_DSP95
DIO10_DSP96: D19.K/A R90.2 R99.2 ; off-sheet DIO10_DSP96
DIO11_DSP97: D20.K/A R91.2 R97.2 ; off-sheet DIO11_DSP97
DIO12_DSP171: D21.K/A R92.2 R100.2 ; off-sheet DIO12_DSP171
DIO13_DSP172: D22.K/A R93.2 R101.2 ; off-sheet DIO13_DSP172
DIO14_DSP175: D23.K/A R94.2 R102.2 ; off-sheet DIO14_DSP175
DIO15_DSP176: D24.K/A R95.2 R103.2 ; off-sheet DIO15_DSP176
N16642513: C95.1 IC15.1 PAD22.1
N16664780: D15.K/A IC13.4 R85.2
N16668564: D16.K/A IC14.2 R86.2 R87.2
N16668568: CN6.3 R87.1
N16669496: CN4.1 IC12.7
N16669500: CN4.2 IC12.6
N16671270: CN6.2 R85.1
N16690596: LED1.A R81.2
N16817849: CN7.9 R103.1
N16817854: CN7.8 R102.1
N16817859: CN7.7 R101.1
N16817864: CN7.6 R100.1
N16817869: CN7.5 R97.1
N16817874: CN7.4 R99.1
N16817879: CN7.3 R98.1
N16817884: CN7.2 R96.1
N16840741: CN7.1 FU2.1
N16841842: CN6.1 FU1.1
SCIRX_B_DSP157: IC14.4 ; off-sheet SCIRX_B_DSP157
SCITX_B_DSP156: IC13.2 R84.2 ; off-sheet SCITX_B_DSP156

Not connected (* = marked no-connect by the designer): CN3 NC1 NC2; CN4 PAD1 PAD2; CN5 PAD1 PAD2; CN6 PAD1 PAD2; CN7 PAD1 PAD2; IC12 5 8; IC13 1; IC14 1

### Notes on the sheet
- (near R96) x4
- x4

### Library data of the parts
C76-C78 C80 C91 C95 = C: as C54 on sheet 2
C79 C81 C82 C84 C87 C88 C92-C94 = C: as C19 on sheet 3
C83 = C: as C1 on sheet 1
C85 C86 C89 C90 C96 C97 = C: as C8 on sheet 1
CN3 = WR-60P: SAVEAREA0: -67682,-998,88845,96631; SAVECOUNT: 3; TIME: 09:42:27; UPDATEUSER: cae; UPDATETIME: 10:25:54; OriginalSymbolOrigin: (5080,91440); CDBNAME: CN-WR-60P-HF-HD-A1E
CN4 = BM03B-PASS: SAVEAREA0: -16737,-296,39143,28727; SAVECOUNT: 24; TIME: 13:28:28; UPDATEUSER: cae; UPDATETIME: 09:56:18; OriginalSymbolOrigin: (2540,25400); CDBNAME: CN-SM03B-PASS-TBT_LF_SN
CN5 = BM02B-PASS: SAVEAREA0: -14164,-269,36638,26116; SAVECOUNT: 26; TIME: 13:28:28; UPDATEUSER: cae; UPDATETIME: 09:55:50; OriginalSymbolOrigin: (2540,22860); CDBNAME: CN-SM02B-PASS-TBT_LF_SN
CN6 = BM04B-PASS: SAVEAREA0: -19295,-323,41666,31339; SAVECOUNT: 22; TIME: 13:28:28; UPDATEUSER: cae; UPDATETIME: 09:56:44; OriginalSymbolOrigin: (2540,27940); CDBNAME: CN-SM04B-PASS-TBT_LF_SN
CN7 = SM10B-PASS: SAVEAREA0: -33411,-485,58033,47009; SAVECOUNT: 23; TIME: 13:28:28; UPDATEUSER: cae; UPDATETIME: 14:27:01; OriginalSymbolOrigin: (2540,43180); CDBNAME: CN-SM10B-PASS-TBT_LF_SN
D15 D16 D20 D21 = 1SS396: as D1 on sheet 1
D17-D19 D22-D24 = 1SS396: SAVECOUNT: 7; SAVEAREA0: -5465,-437,27678,21425; TIME: 18:51:12; UPDATEUSER: cae; UPDATETIME: 10:39:29; OriginalSymbolOrigin: (5080,17780); USERCOMPTEXT3: TOSHIBA; CDBNAME: D-1SS396_AK
FU1 FU2 = F: OriginalSymbolOrigin: (2540,5080); CDBNAME: FU-CCF1N1.6TTE
IC11 = VHC540: SAVEAREA0: -64373,-927,110287,89788; TIME: 09:37:32; UPDATEUSER: cae; SAVECOUNT: 1; OriginalSymbolOrigin: (7620,83820); CDBNAME: IC-TC74VHC540FT
IC12 = TCAN332D: SAVECOUNT: 26; SAVEAREA0: -15475,-323,45487,31339; TIME: 17:47:02; UPDATEUSER: cae; UPDATETIME: 14:38:54; OriginalSymbolOrigin: (5080,27940); CDBNAME: IC-TCAN332D
IC13 IC14 = CL1G017: as IC8 on sheet 2
IC15 = REF: SAVECOUNT: 25; SAVEAREA0: -10386,-296,45494,28727; TIME: 17:47:02; UPDATEUSER: cae; UPDATETIME: 11:05:59; OriginalSymbolOrigin: (5080,25400); CDBNAME: IC-REF2030AIDDCT
L1 = L: OriginalSymbolOrigin: (2540,5080); CDBNAME: L-MMZ2012S601AT000
LED1 = VCDG1111C: SAVEAREA0: -6769,-859,19276,16321; TIME: 14:49:55; UPDATEUSER: cae; UPDATETIME: 10:51:12; SAVECOUNT: 5; OriginalSymbolOrigin: (5080,7620); CDBNAME: LED-VCDG1111C-4BY3C-TR
PAD10 PAD18-PAD22 = TP: as PAD1 on sheet 2
PAD11-PAD17 = TP: as PAD2 on sheet 2
PS1 = L15AG: TIME: 08:44:39; UPDATEUSER: cae; UPDATETIME: 13:17:54; SAVECOUNT: 102; SAVEAREA0: -14581,-371,55282,35914; OriginalSymbolOrigin: (7620,33020); CDBNAME: PS-TCR15AG33
PS2 = L15AG: TIME: 08:44:39; UPDATEUSER: cae; UPDATETIME: 13:17:54; SAVECOUNT: 102; SAVEAREA0: -14581,-371,55282,35914; OriginalSymbolOrigin: (7620,33020); CDBNAME: PS-TCR15AG12
R74-R80 R82-R84 R86 R88-R95 = R: as R5 on sheet 1
R81 = R: OriginalSymbolOrigin: (5080,5080); CDBNAME: R-ERJ3EKF4700V; USERCOMPTEXT1: 1608
R85 R87 R96-R103 = R: as R11 on sheet 1
U?#4 = WAKU_DEF100_2018: as U?#3 on sheet 3

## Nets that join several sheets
1.2V: 1 (21 pins), 4 (5 pins)
3.3V: 1 (75 pins), 3 (14 pins), 4 (33 pins)
3.3VA: 1 (6 pins), 4 (5 pins)
3V_REF: 1 (10 pins), 4 (C91.1 IC15.5 PAD20.1)
5V: 2 (8 pins), 4 (35 pins)
GND: 1 (80 pins), 2 (40 pins), 3 (48 pins), 4 (65 pins)
/DO0_BO: 2 (IC7.11 PAD8.1), 4 (CN3.41)
/DO1_BO: 2 (IC7.12 PAD7.1), 4 (CN3.42)
/DO2_BO: 2 (IC7.13 PAD6.1), 4 (CN3.43)
/DO3_BO: 2 (IC7.14 PAD5.1), 4 (CN3.44)
/DO4_BO: 2 (IC7.15 PAD4.1), 4 (CN3.45)
/DO5_BO: 2 (IC7.16 PAD3.1), 4 (CN3.46)
/DO6_BO: 2 (IC7.17 PAD2.1), 4 (CN3.47)
/DO7_BO: 2 (IC7.18 PAD1.1), 4 (CN3.48)
/PWM1A_BO: 2 (IC5.13 TP6.1), 4 (CN3.25)
/PWM1B_BO: 2 (IC5.14 TP5.1), 4 (CN3.26)
/PWM2A_BO: 2 (IC5.15 TP4.1), 4 (CN3.27)
/PWM2B_BO: 2 (IC5.16 TP3.1), 4 (CN3.28)
/PWM3A_BO: 2 (IC5.17 TP2.1), 4 (CN3.29)
/PWM3B_BO: 2 (IC5.18 TP1.1), 4 (CN3.30)
/PWM4A_BO: 2 (IC6.13 TP12.1), 4 (CN3.33)
/PWM4B_BO: 2 (IC6.14 TP11.1), 4 (CN3.34)
/PWM5A_BO: 2 (IC6.15 TP10.1), 4 (CN3.35)
/PWM5B_BO: 2 (IC6.16 TP9.1), 4 (CN3.36)
/PWM6A_BO: 2 (IC6.17 TP8.1), 4 (CN3.37)
/PWM6B_BO: 2 (IC6.18 TP7.1), 4 (CN3.38)
/RESET_BO: 2 (IC8.4 PAD9.1), 4 (CN3.49)
/RESET_SIG: 1 (IC2.4 IC3.124 R7.2), 2 (IC8.2)
AD0: 3 (R50.2), 4 (CN3.9)
AD1: 3 (R54.2), 4 (CN3.10)
AD2: 3 (R55.1), 4 (CN3.13)
AD3: 3 (R51.1), 4 (CN3.14)
AD4: 3 (R62.2), 4 (CN3.17)
AD5: 3 (R66.2), 4 (CN3.18)
AD6: 3 (R67.1), 4 (CN3.21)
AD7: 3 (R63.1), 4 (CN3.22)
ADC01_P_DSP41: 1 (IC3.41), 3 (C63.1 R58.1)
ADC02_P_DSP39: 1 (IC3.39), 3 (C65.1 R60.1)
ADC03_P_DSP48: 1 (IC3.48), 3 (C64.1 R59.1)
ADC04_P_DSP44: 1 (IC3.44), 3 (C66.1 R61.1)
ADC05_P_DSP31: 1 (IC3.31 IC3.40), 3 (C72.1 R70.1)
ADC06_P_DSP29: 1 (IC3.29 IC3.49), 3 (C74.1 R72.1)
ADC07_P_DSP56: 1 (IC3.56), 3 (C73.1 R71.1)
ADC08_P_DSP58: 1 (IC3.58), 3 (C75.1 R73.1)
BOOT1_DSP: 1 (CN2.14 R17.2), 3 (R29.2 SW2.3)
BOOT1_DSP139: 1 (IC3.139), 3 (R29.1)
CANRX_A_DSP83: 1 (IC3.83), 4 (IC12.4)
CANTX_A_DSP84: 1 (IC3.84), 4 (IC12.1 R83.2)
DI0_DSP132: 1 (IC3.132), 4 (IC11.18 PAD10.1)
DI1_DSP133: 1 (IC3.133), 4 (IC11.17 PAD11.1)
DI2_DSP140: 1 (IC3.140), 4 (IC11.16 PAD12.1)
DI3_DSP141: 1 (IC3.141), 4 (IC11.15 PAD13.1)
DI4_DSP142: 1 (IC3.142), 4 (IC11.14 PAD14.1)
DI5_DSP143: 1 (IC3.143), 4 (IC11.13 PAD15.1)
DI6_DSP144: 1 (IC3.144), 4 (IC11.12 PAD16.1)
DI7_DSP145: 1 (IC3.145), 4 (IC11.11 PAD17.1)
DIO08_DSP94: 1 (IC3.94), 4 (D17.K/A R88.2 R96.2)
DIO09_DSP95: 1 (IC3.95), 4 (D18.K/A R89.2 R98.2)
DIO10_DSP96: 1 (IC3.96), 4 (D19.K/A R90.2 R99.2)
DIO11_DSP97: 1 (IC3.97), 4 (D20.K/A R91.2 R97.2)
DIO12_DSP171: 1 (IC3.171), 4 (D21.K/A R92.2 R100.2)
DIO13_DSP172: 1 (IC3.172), 4 (D22.K/A R93.2 R101.2)
DIO14_DSP175: 1 (IC3.175), 4 (D23.K/A R94.2 R102.2)
DIO15_DSP176: 1 (IC3.176), 4 (D24.K/A R95.2 R103.2)
DO0_DSP8: 1 (IC3.8), 2 (IC7.9 R49.1)
DO1_DSP9: 1 (IC3.9), 2 (IC7.8 R48.1)
DO2_DSP10: 1 (IC3.10), 2 (IC7.7 R47.1)
DO3_DSP12: 1 (IC3.12), 2 (IC7.6 R46.1)
DO4_DSP13: 1 (IC3.13), 2 (IC7.5 R45.1)
DO5_DSP14: 1 (IC3.14), 2 (IC7.4 R44.1)
DO6_DSP22: 1 (IC3.22), 2 (IC7.3 R43.1)
DO7_DSP23: 1 (IC3.23), 2 (IC7.2 R42.1)
PWM1A_DSP160: 1 (IC3.160), 2 (IC5.7 R35.1)
PWM1B_DSP161: 1 (IC3.161), 2 (IC5.6 R34.1)
PWM2A_DSP162: 1 (IC3.162), 2 (IC5.5 R33.1)
PWM2B_DSP163: 1 (IC3.163), 2 (IC5.4 R32.1)
PWM3A_DSP164: 1 (IC3.164), 2 (IC5.3 R31.1)
PWM3B_DSP165: 1 (IC3.165), 2 (IC5.2 R30.1)
PWM4A_DSP166: 1 (IC3.166), 2 (IC6.7 R41.1)
PWM4B_DSP167: 1 (IC3.167), 2 (IC6.6 R40.1)
PWM5A_DSP18: 1 (IC3.18), 2 (IC6.5 R39.1)
PWM5B_DSP19: 1 (IC3.19), 2 (IC6.4 R38.1)
PWM6A_DSP1: 1 (IC3.1), 2 (IC6.3 R37.1)
PWM6B_DSP2: 1 (IC3.2), 2 (IC6.2 R36.1)
SCIRX_B_DSP157: 1 (IC3.157), 4 (IC14.4)
SCITX_B_DSP156: 1 (IC3.156), 4 (IC13.2 R84.2)
SCITXDA_DSP154: 1 (CN2.1 IC3.154), 3 (R28.1)
SCL_A_DSP131: 1 (IC3.131), 3 (IC4.6 R20.1)
SDA_A_DSP130: 1 (IC3.130), 3 (IC4.5 R21.1)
